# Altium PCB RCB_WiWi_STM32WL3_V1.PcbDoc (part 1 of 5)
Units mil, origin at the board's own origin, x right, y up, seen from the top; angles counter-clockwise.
Board outline 1250.1 x 2647.64 mil, 10 copper layers (L01-TOP, L02-GND, L03-SIG, L04-GND, L05-PWR, L06-PWR, L07-GND, L08-SIG, L09-GND, L10-BOT), stack 62.1 mil thick; 342 components, 203 nets, 969 pads, 708 vias.
Unrouted connection lines stored in the file: 108.
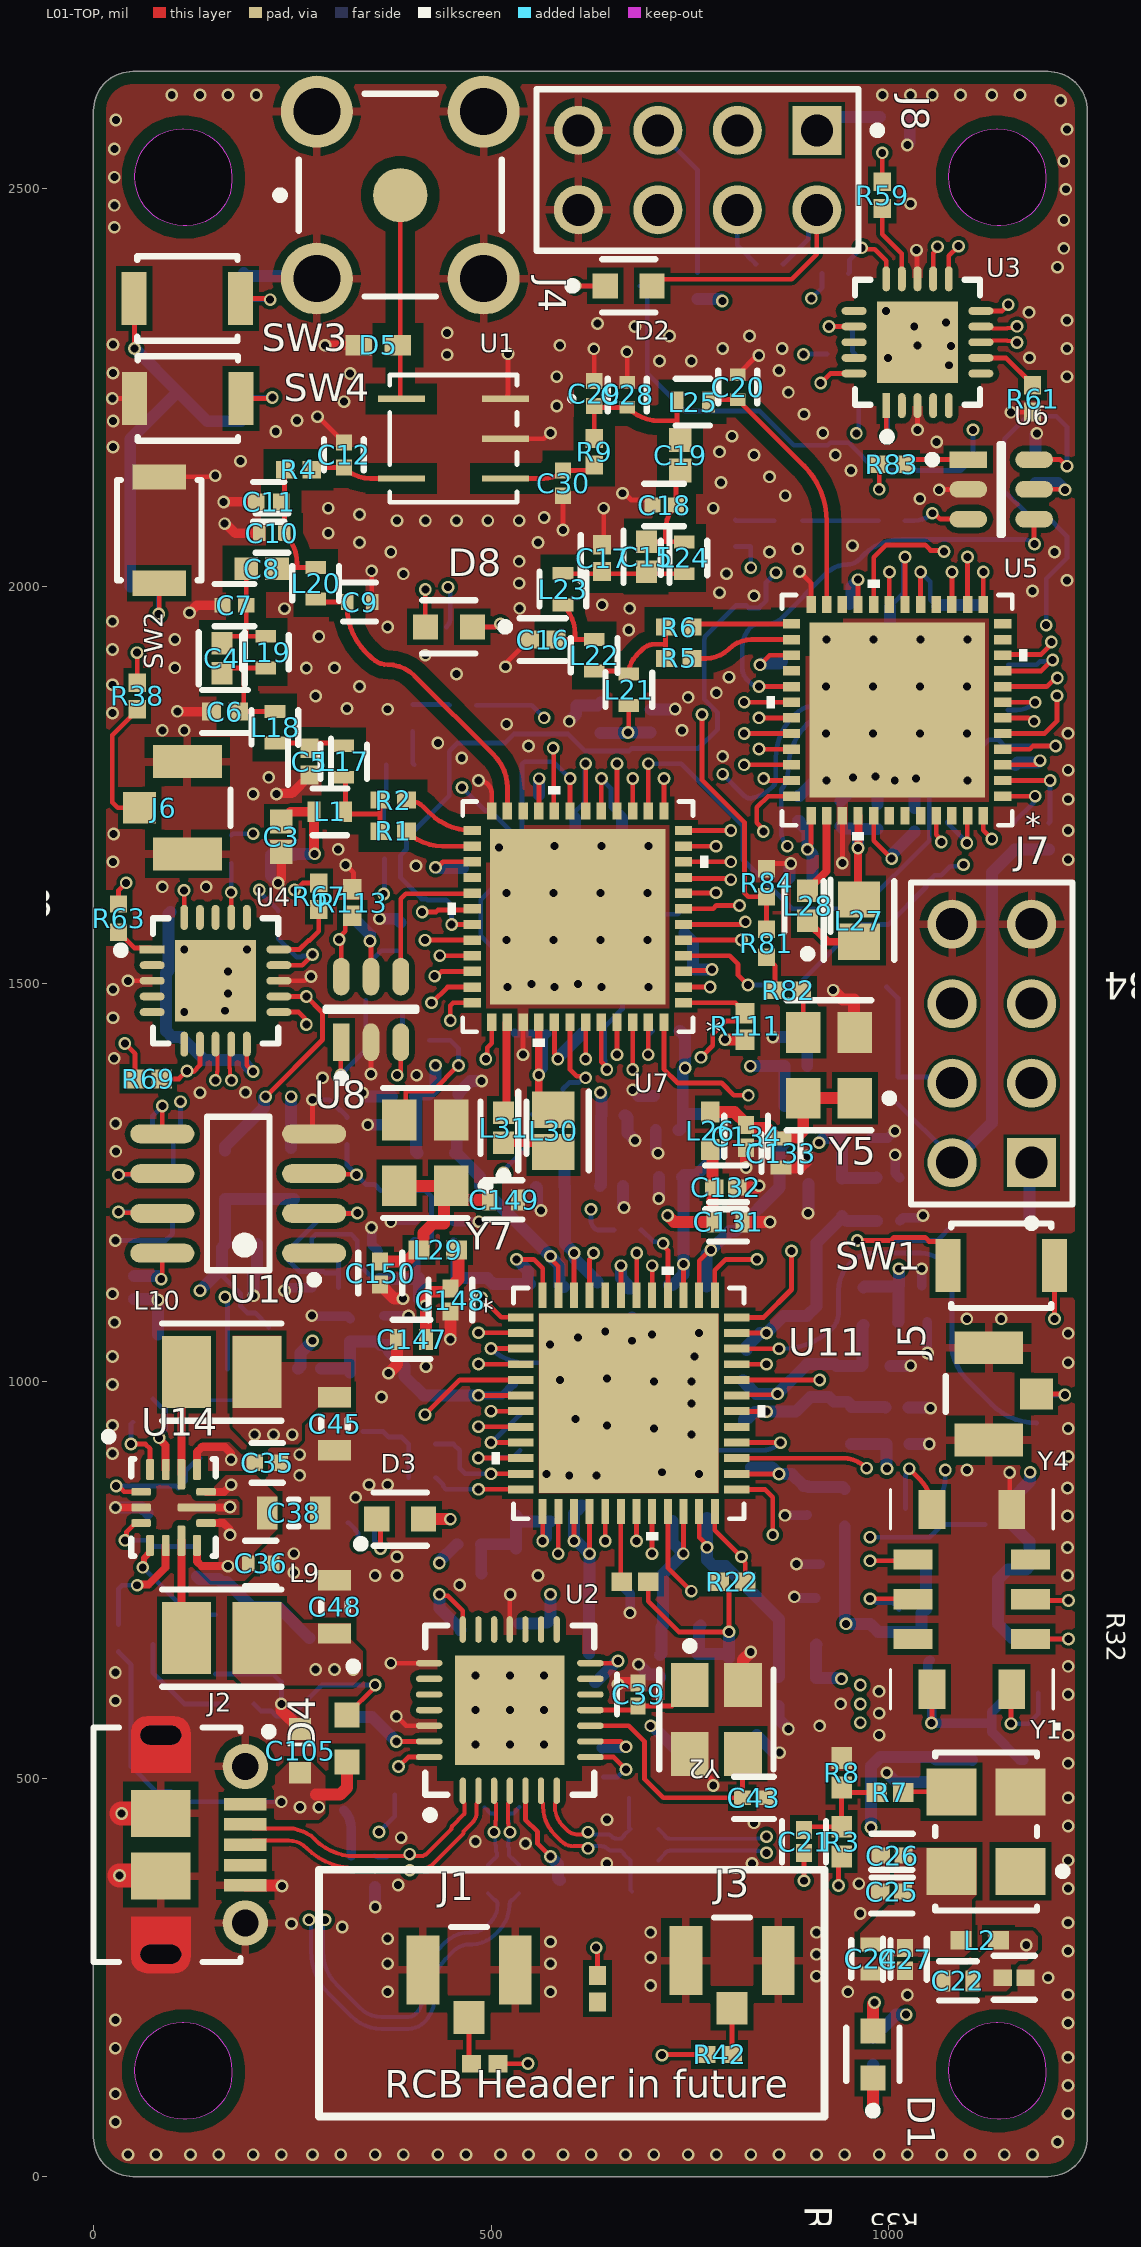
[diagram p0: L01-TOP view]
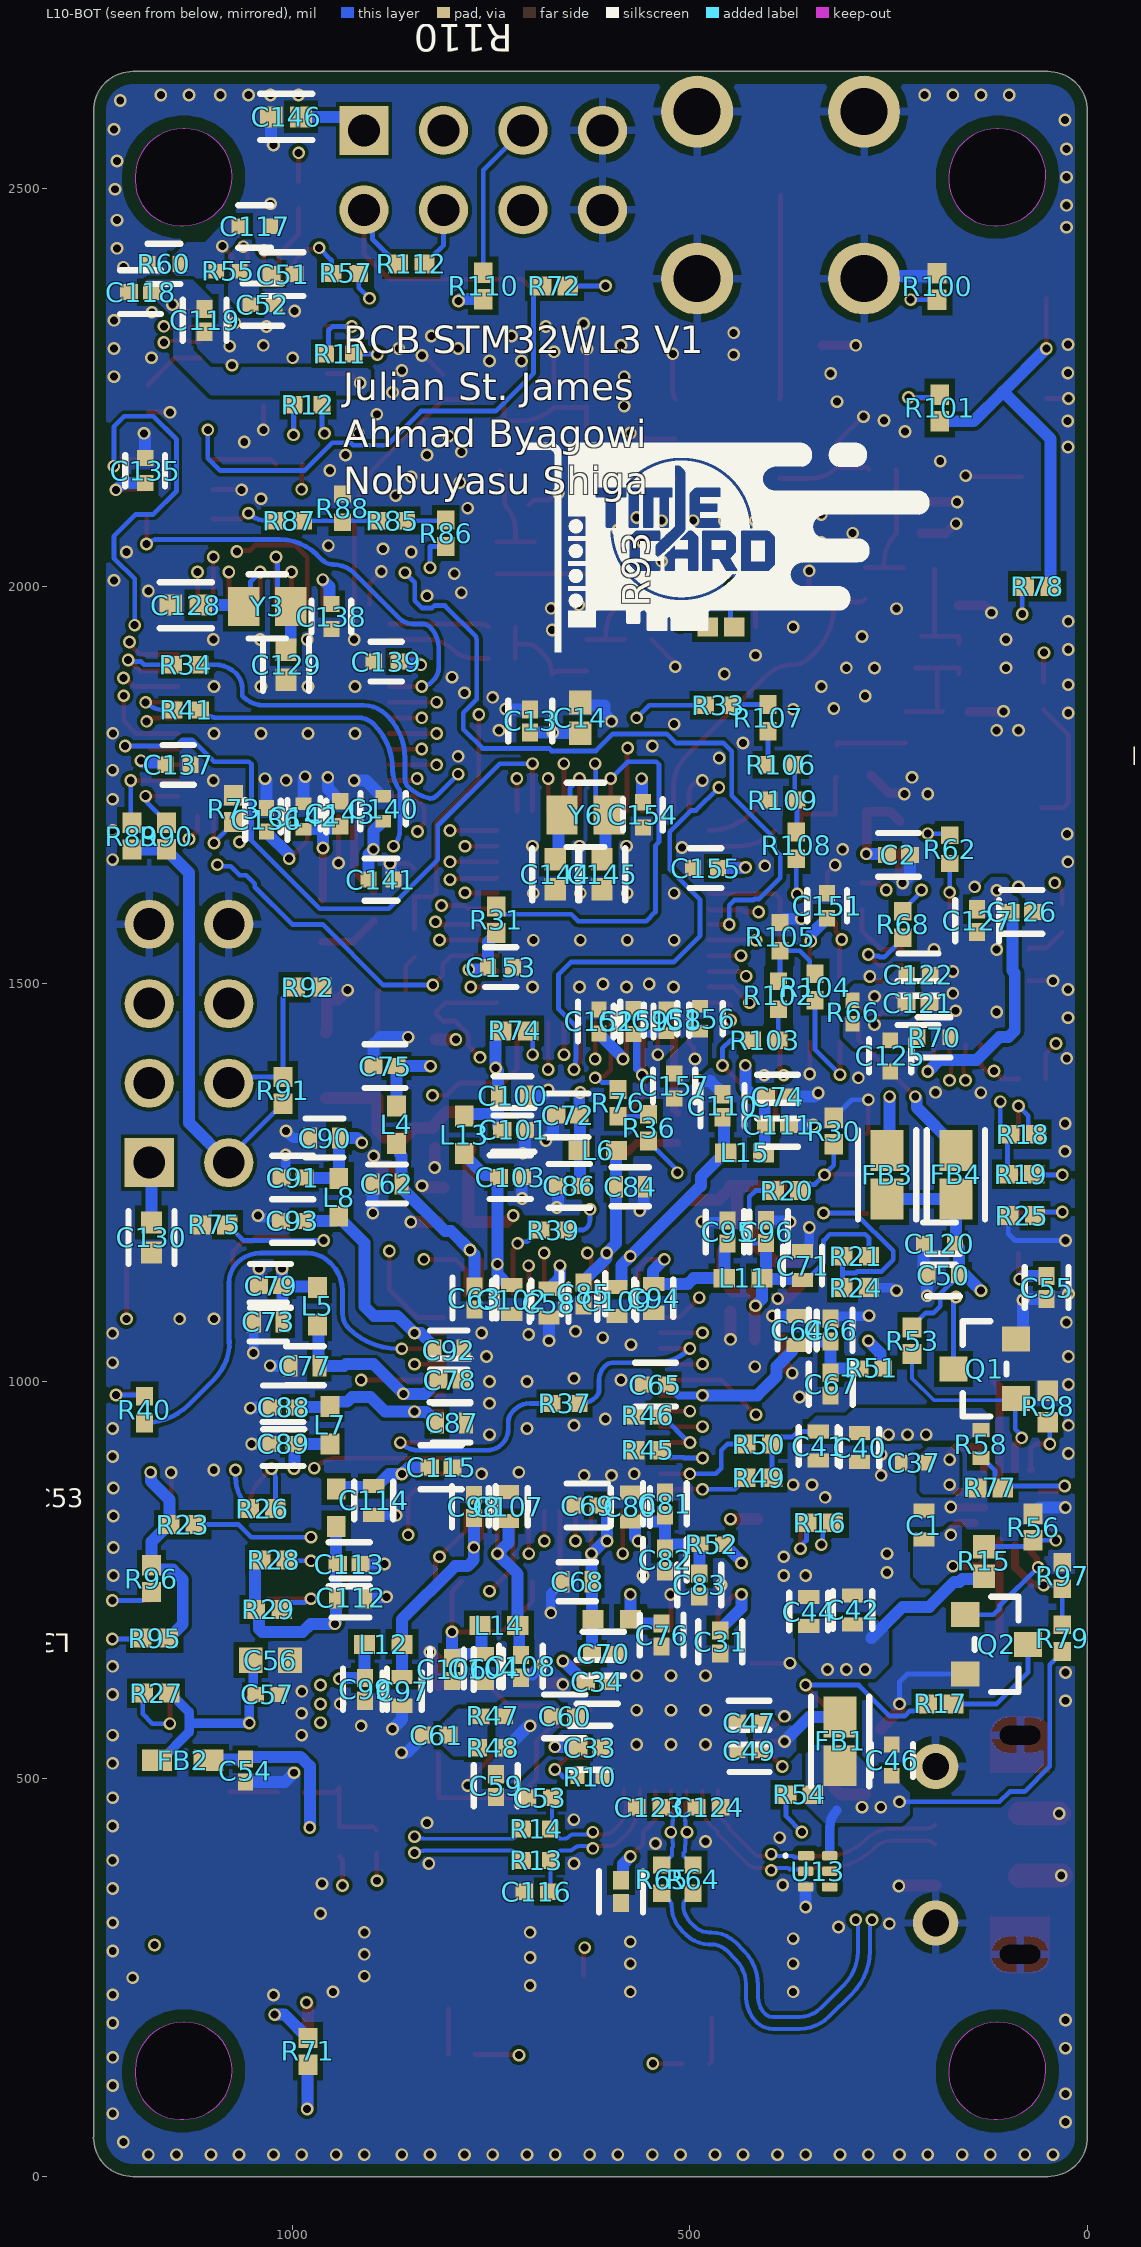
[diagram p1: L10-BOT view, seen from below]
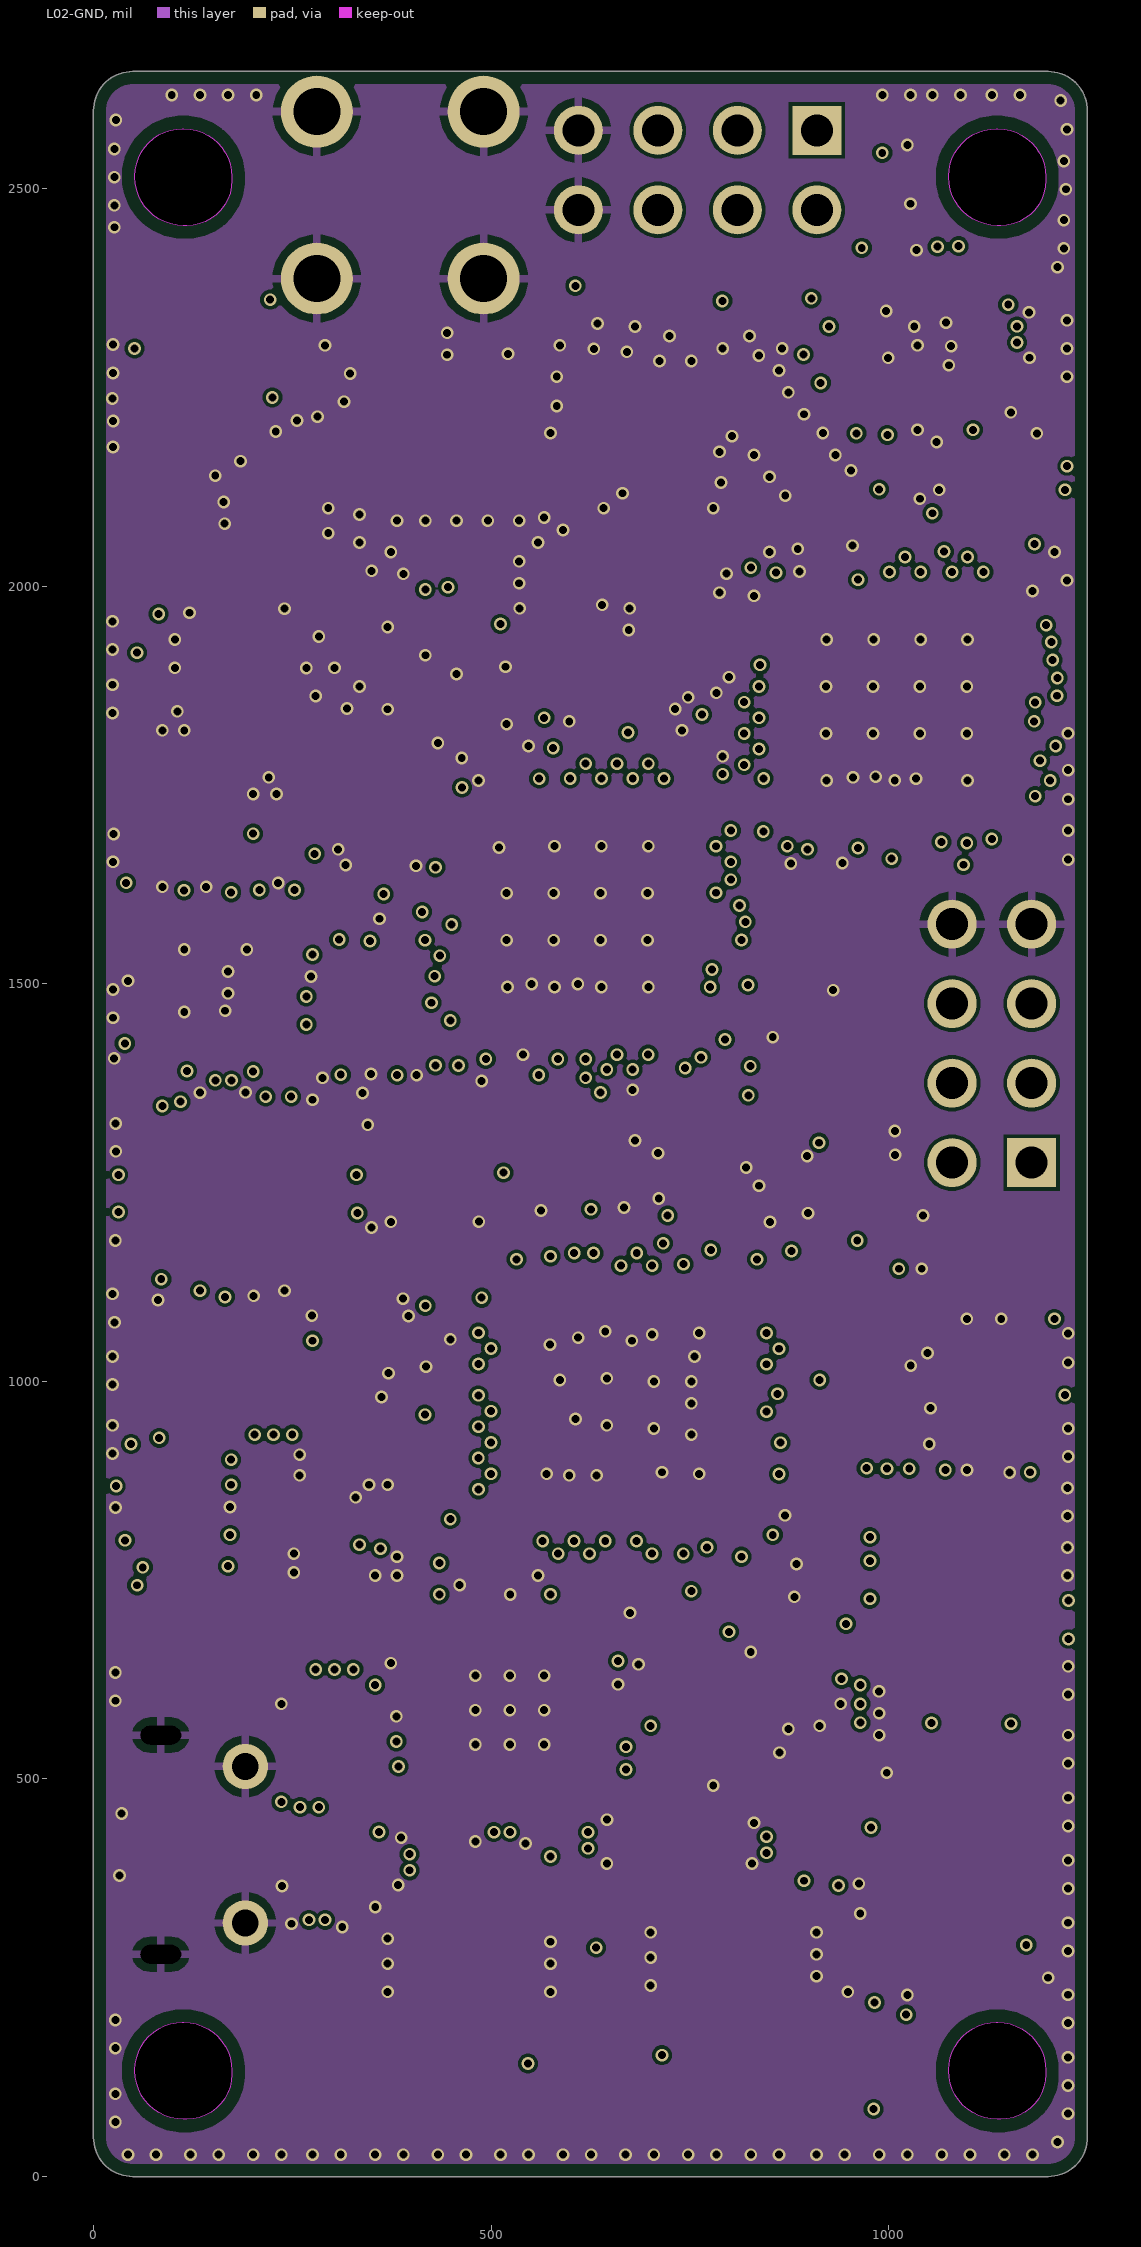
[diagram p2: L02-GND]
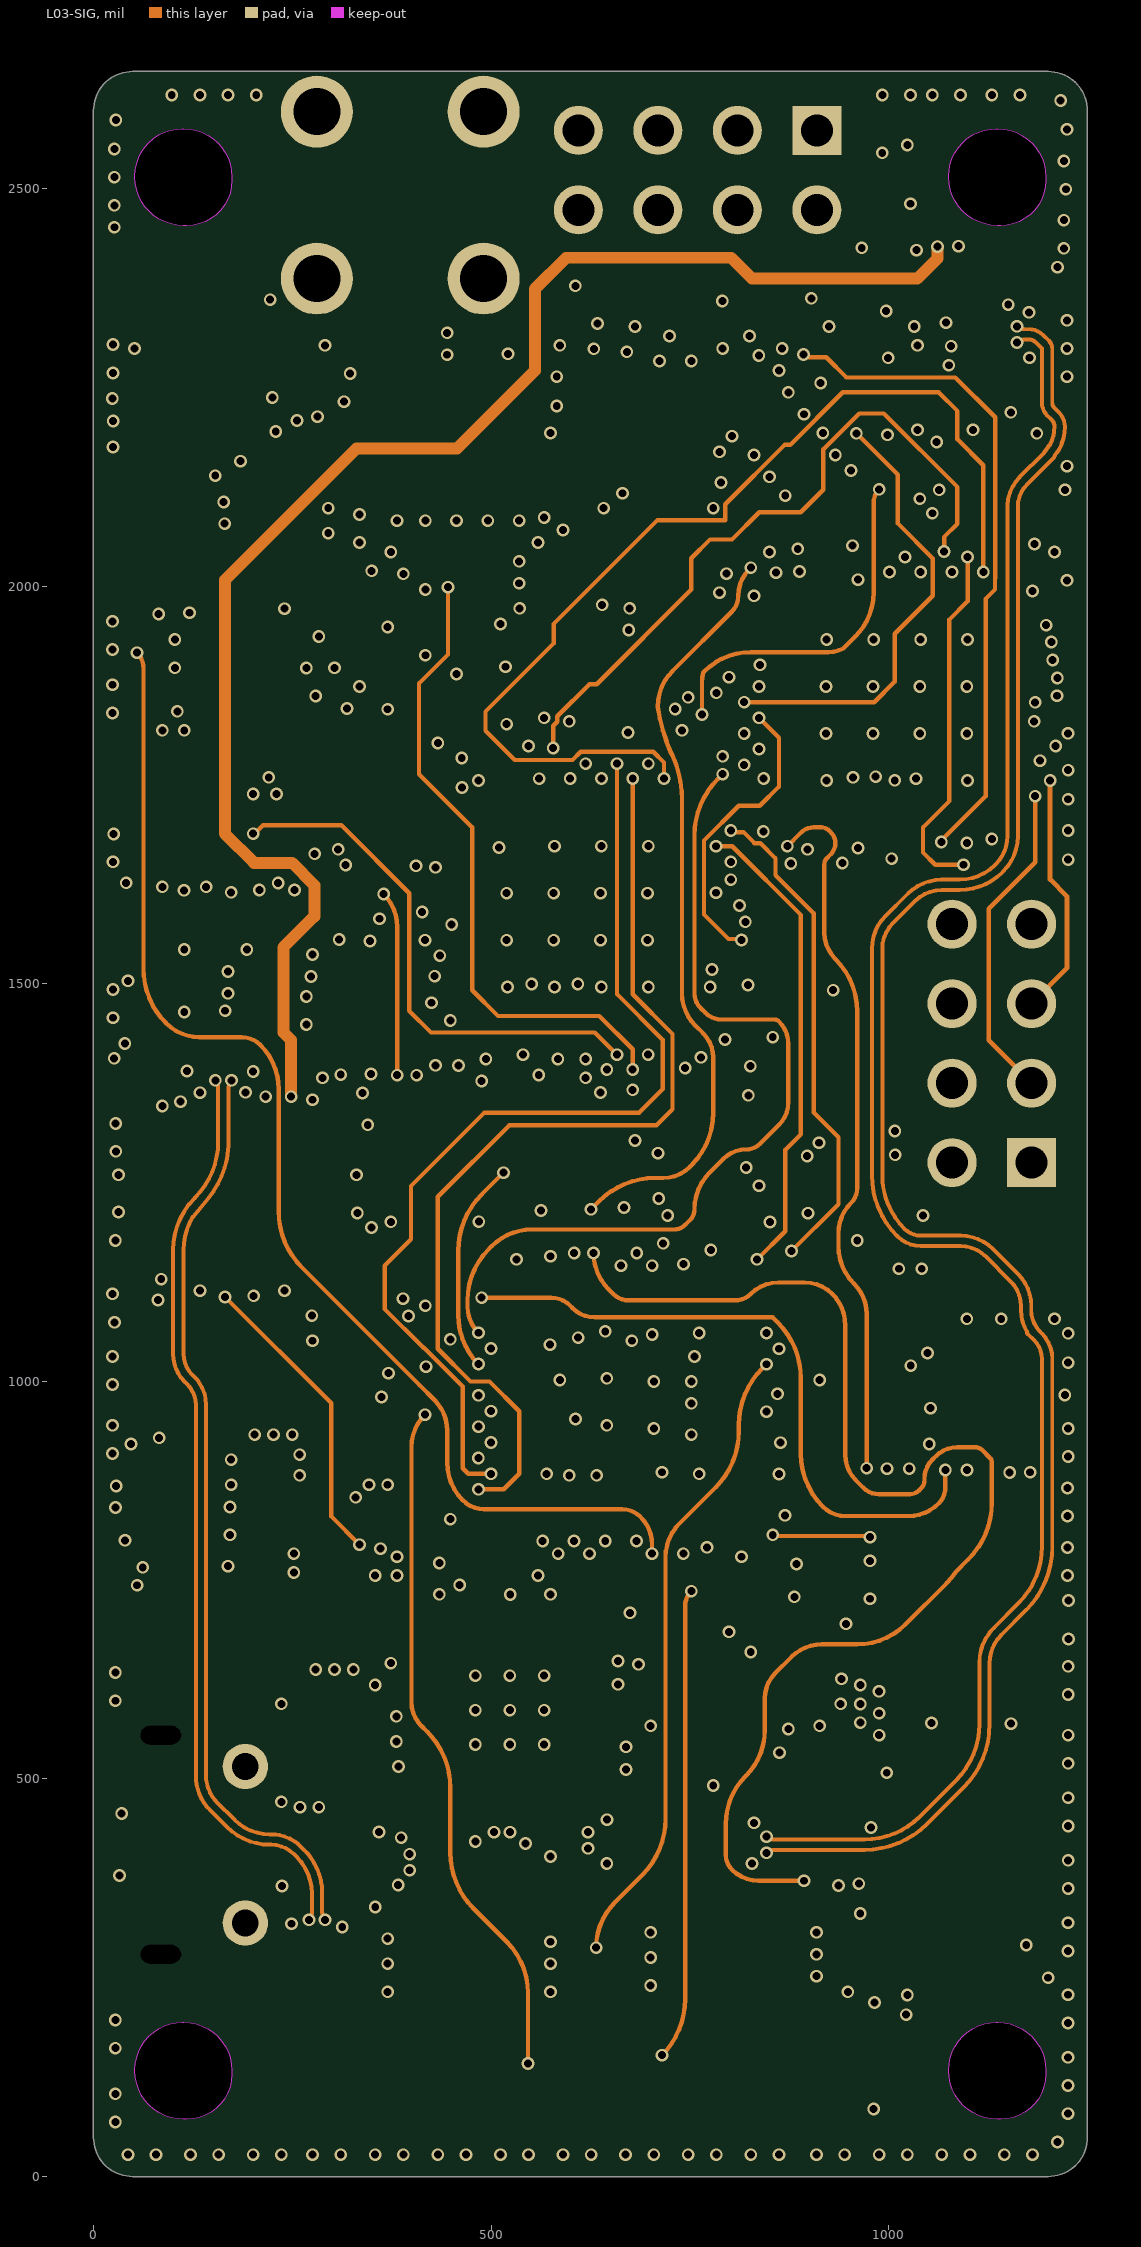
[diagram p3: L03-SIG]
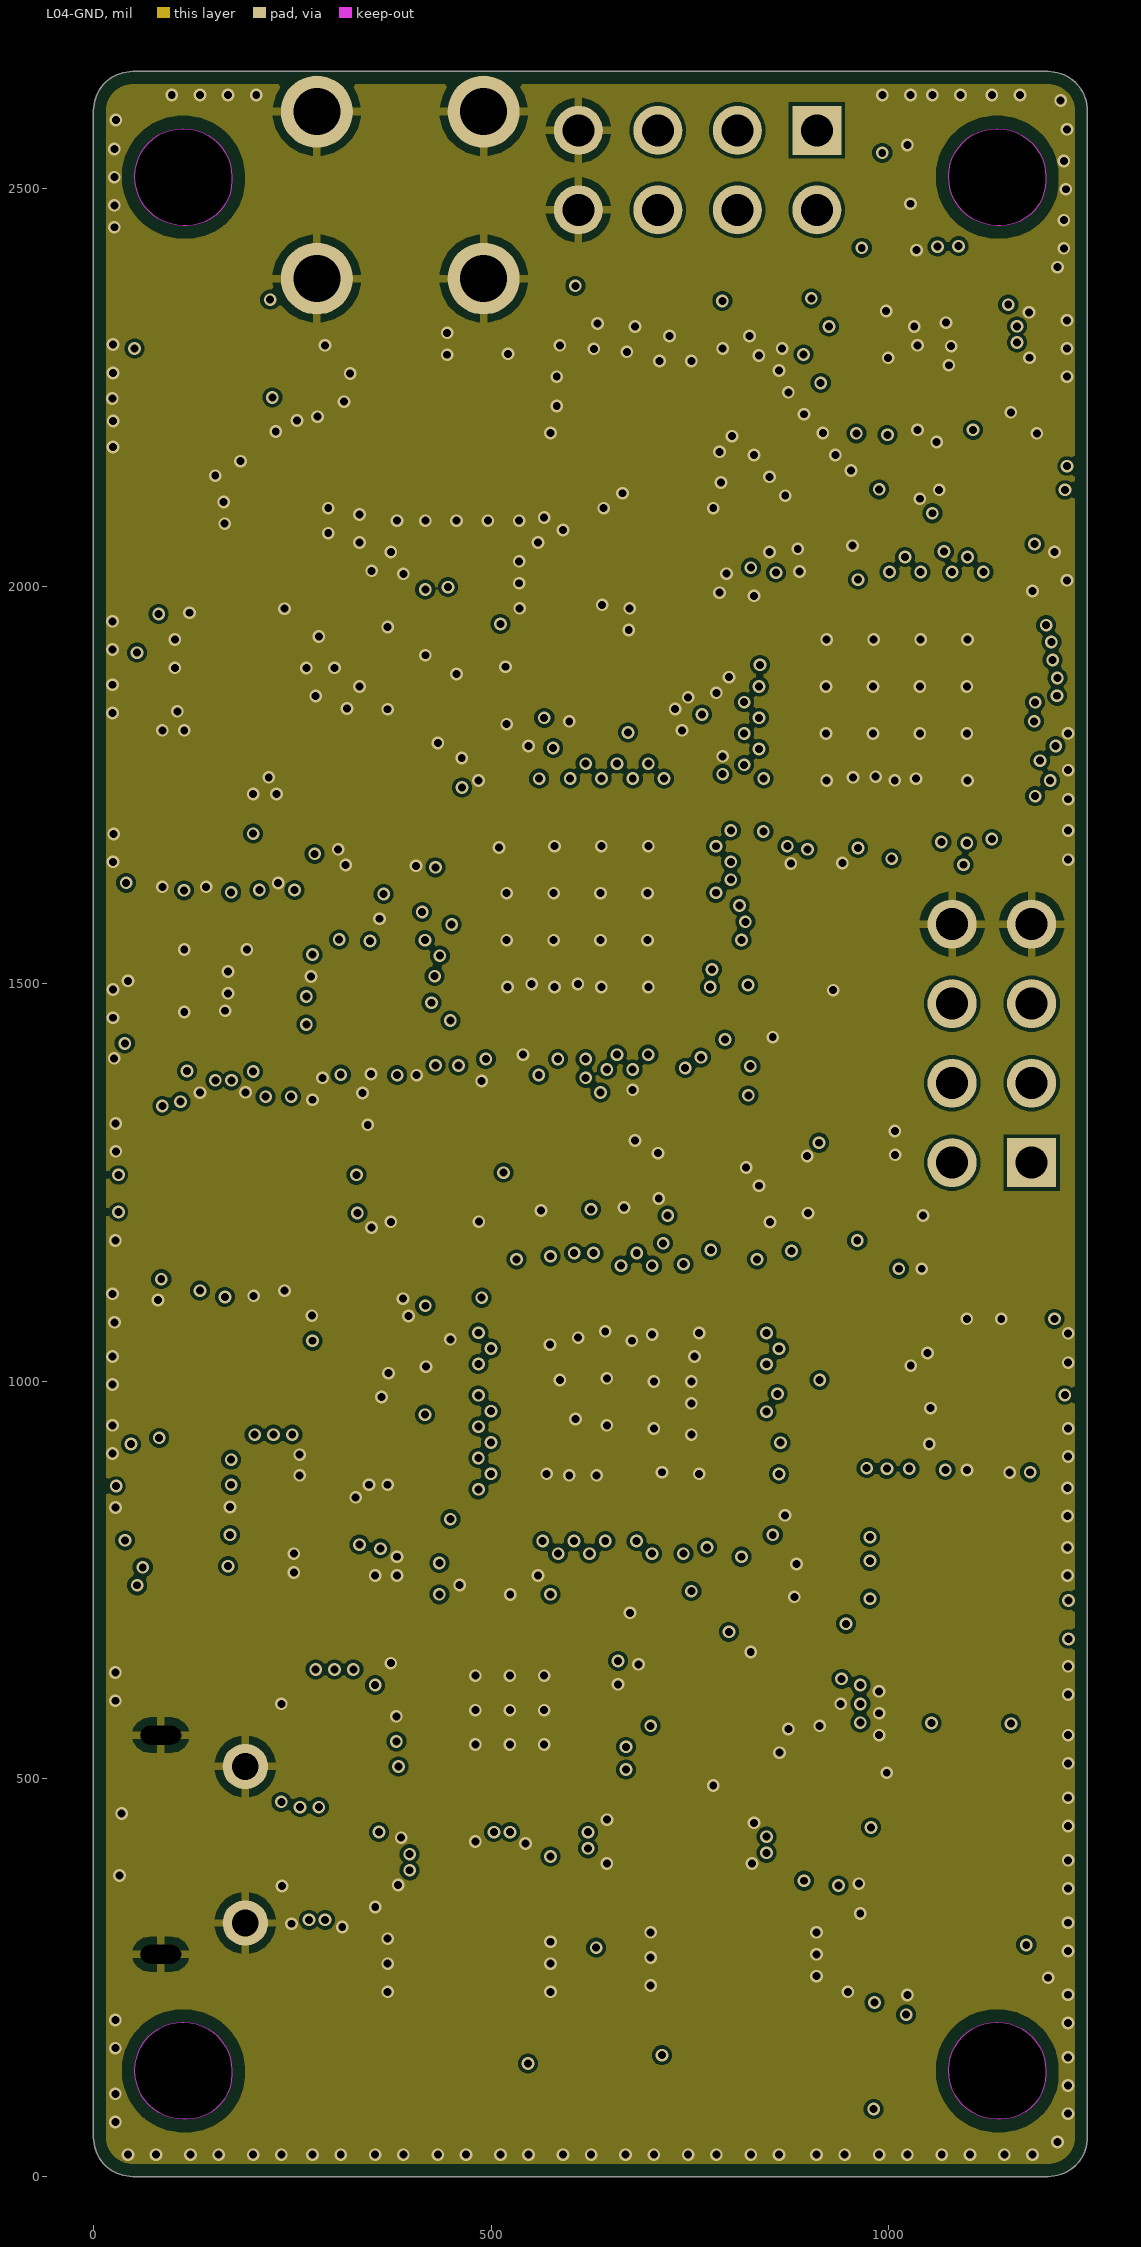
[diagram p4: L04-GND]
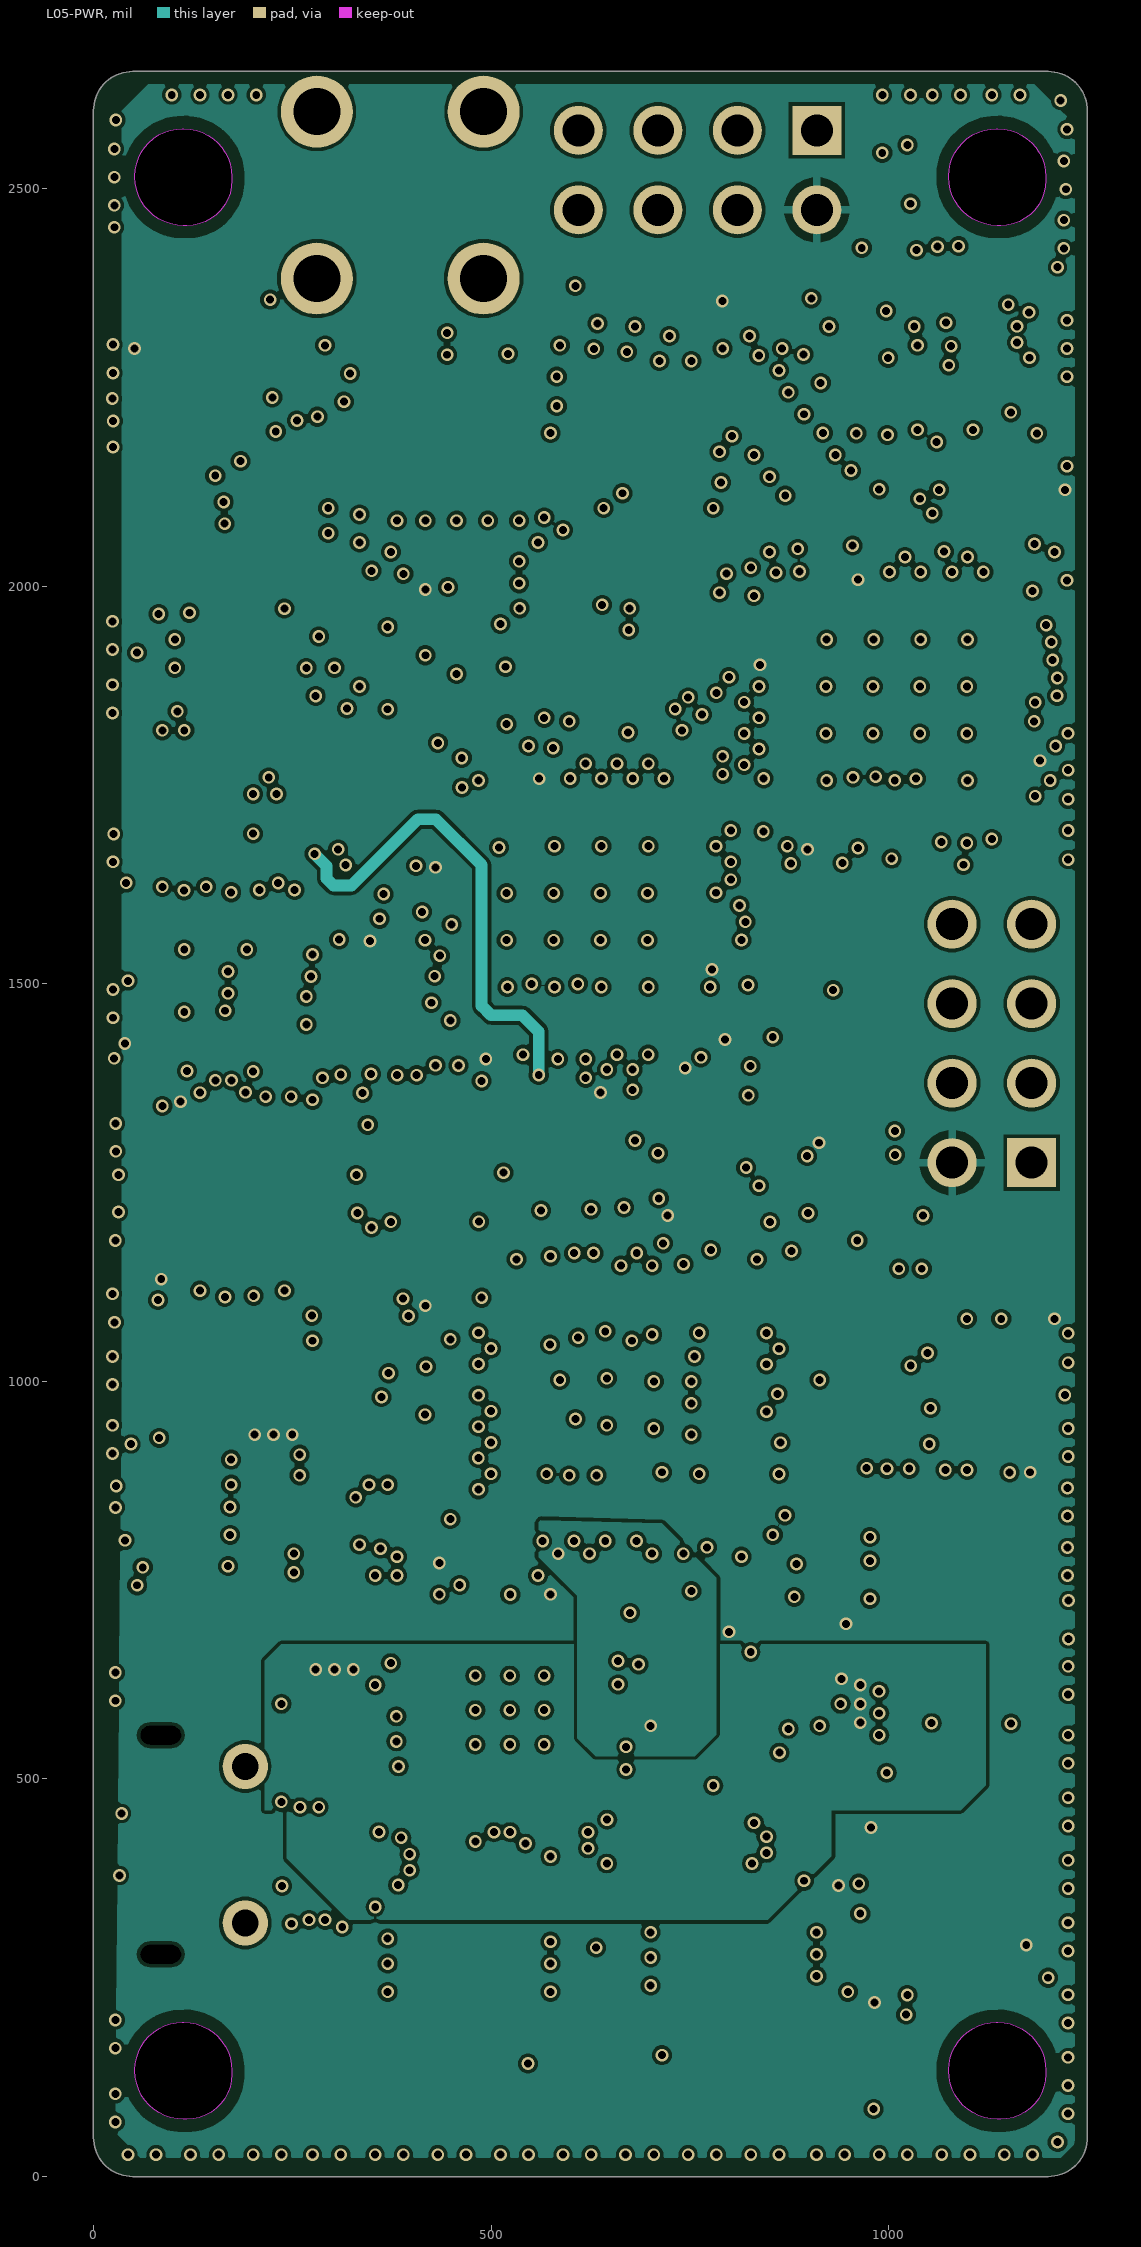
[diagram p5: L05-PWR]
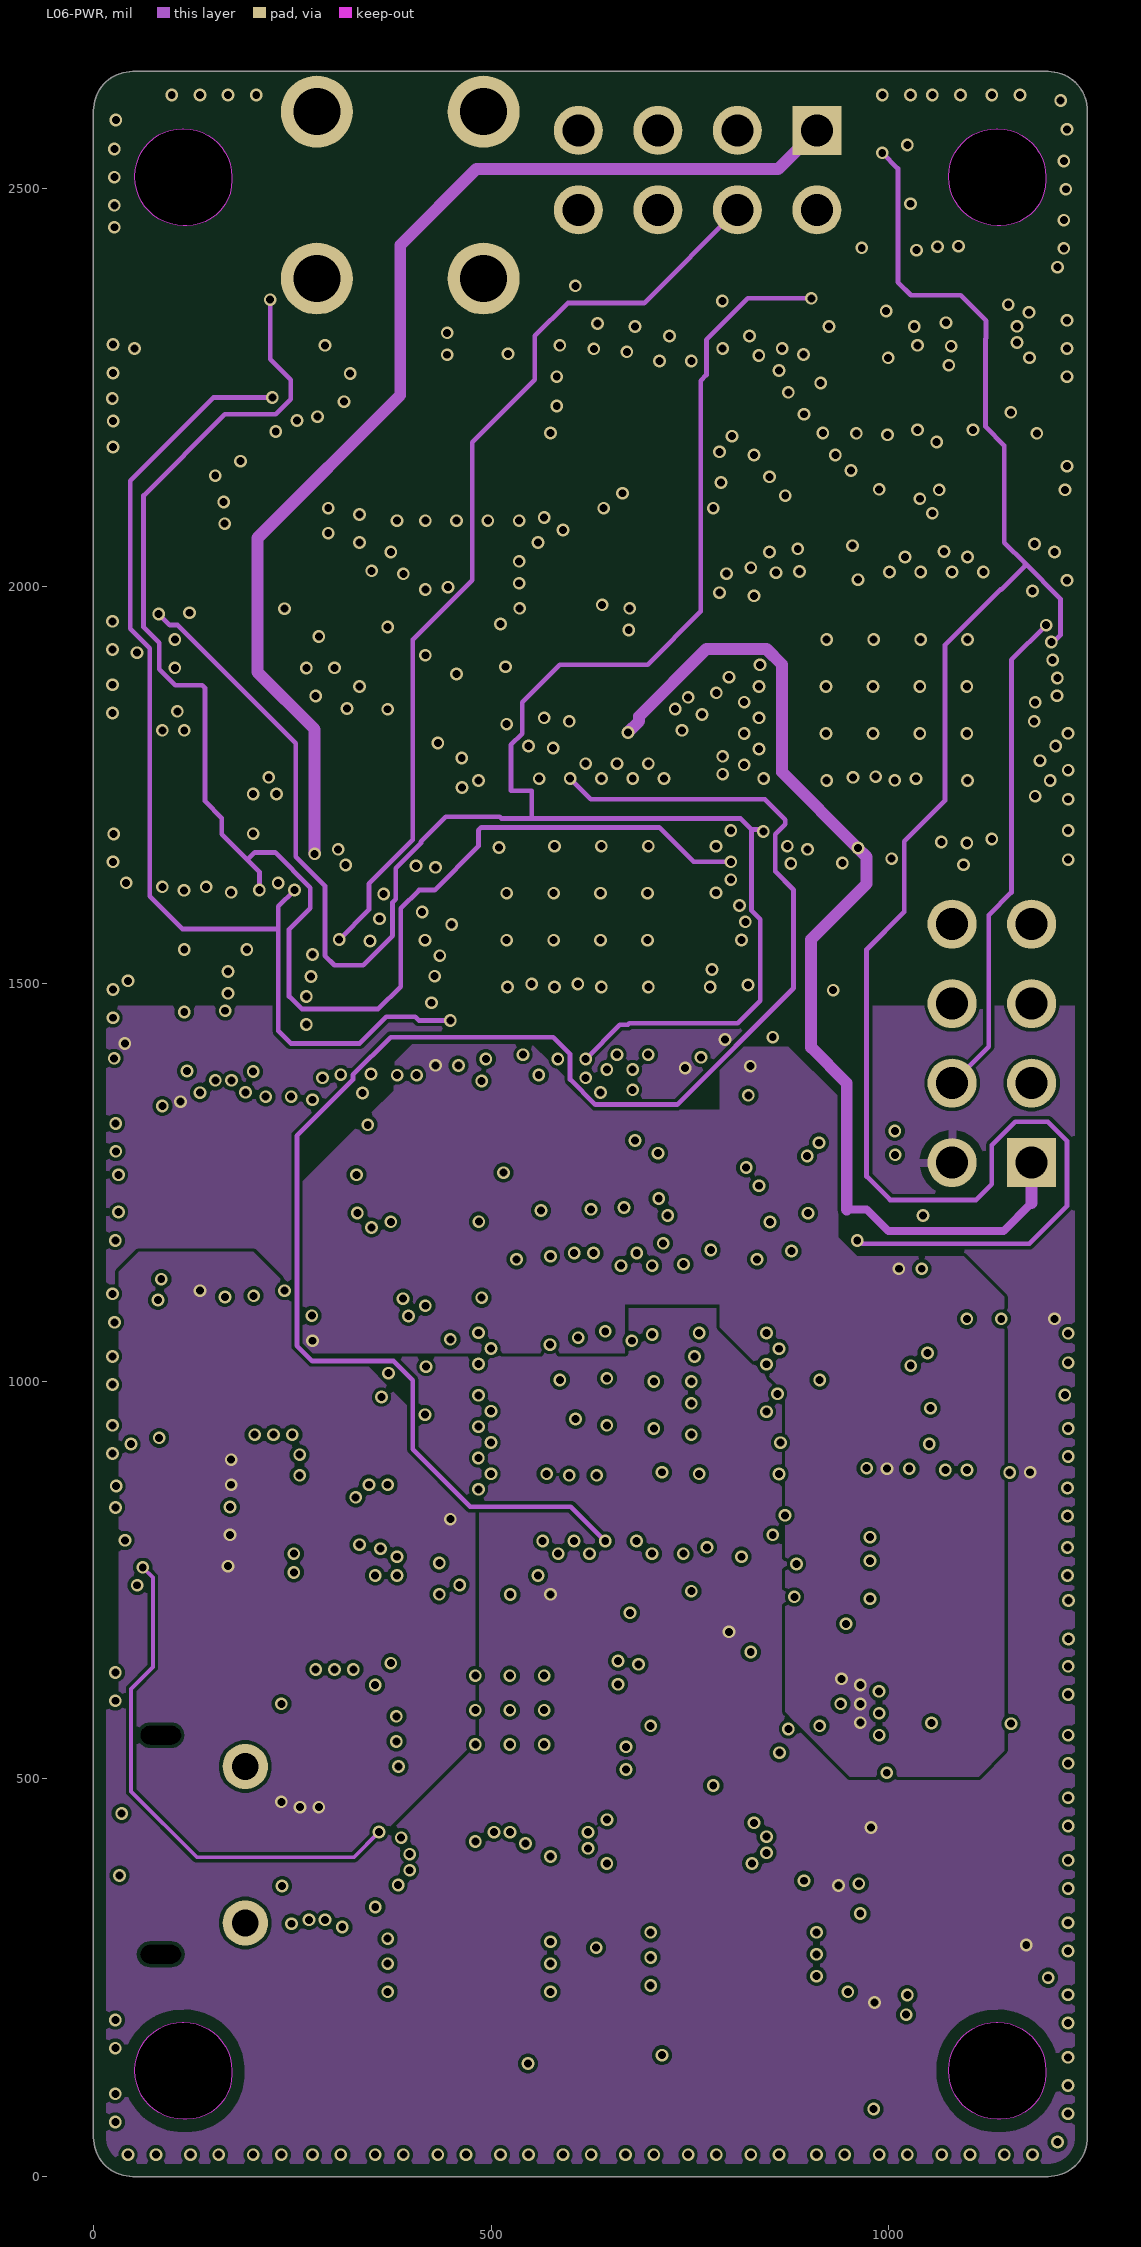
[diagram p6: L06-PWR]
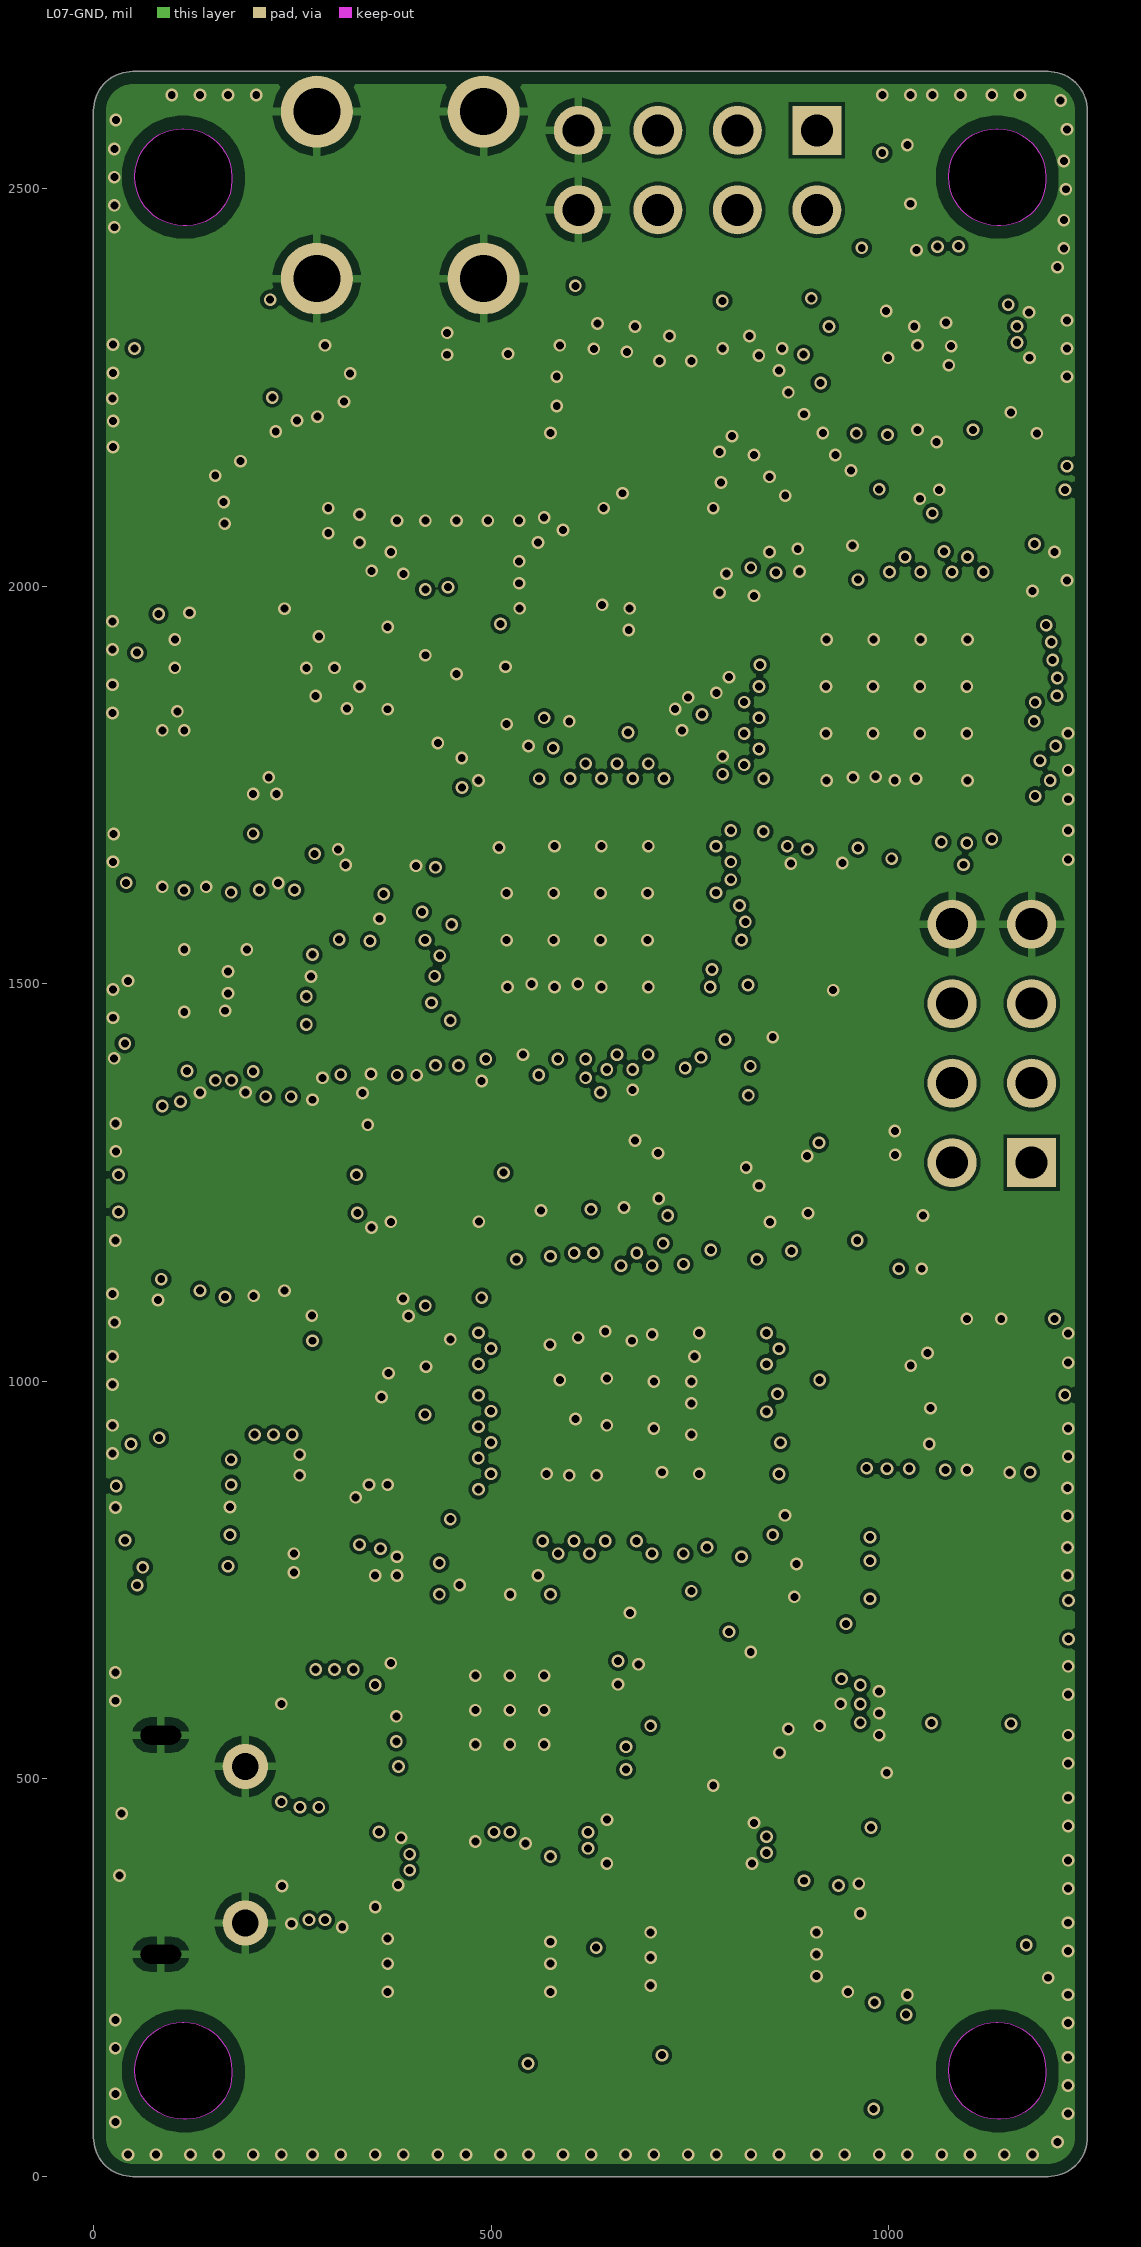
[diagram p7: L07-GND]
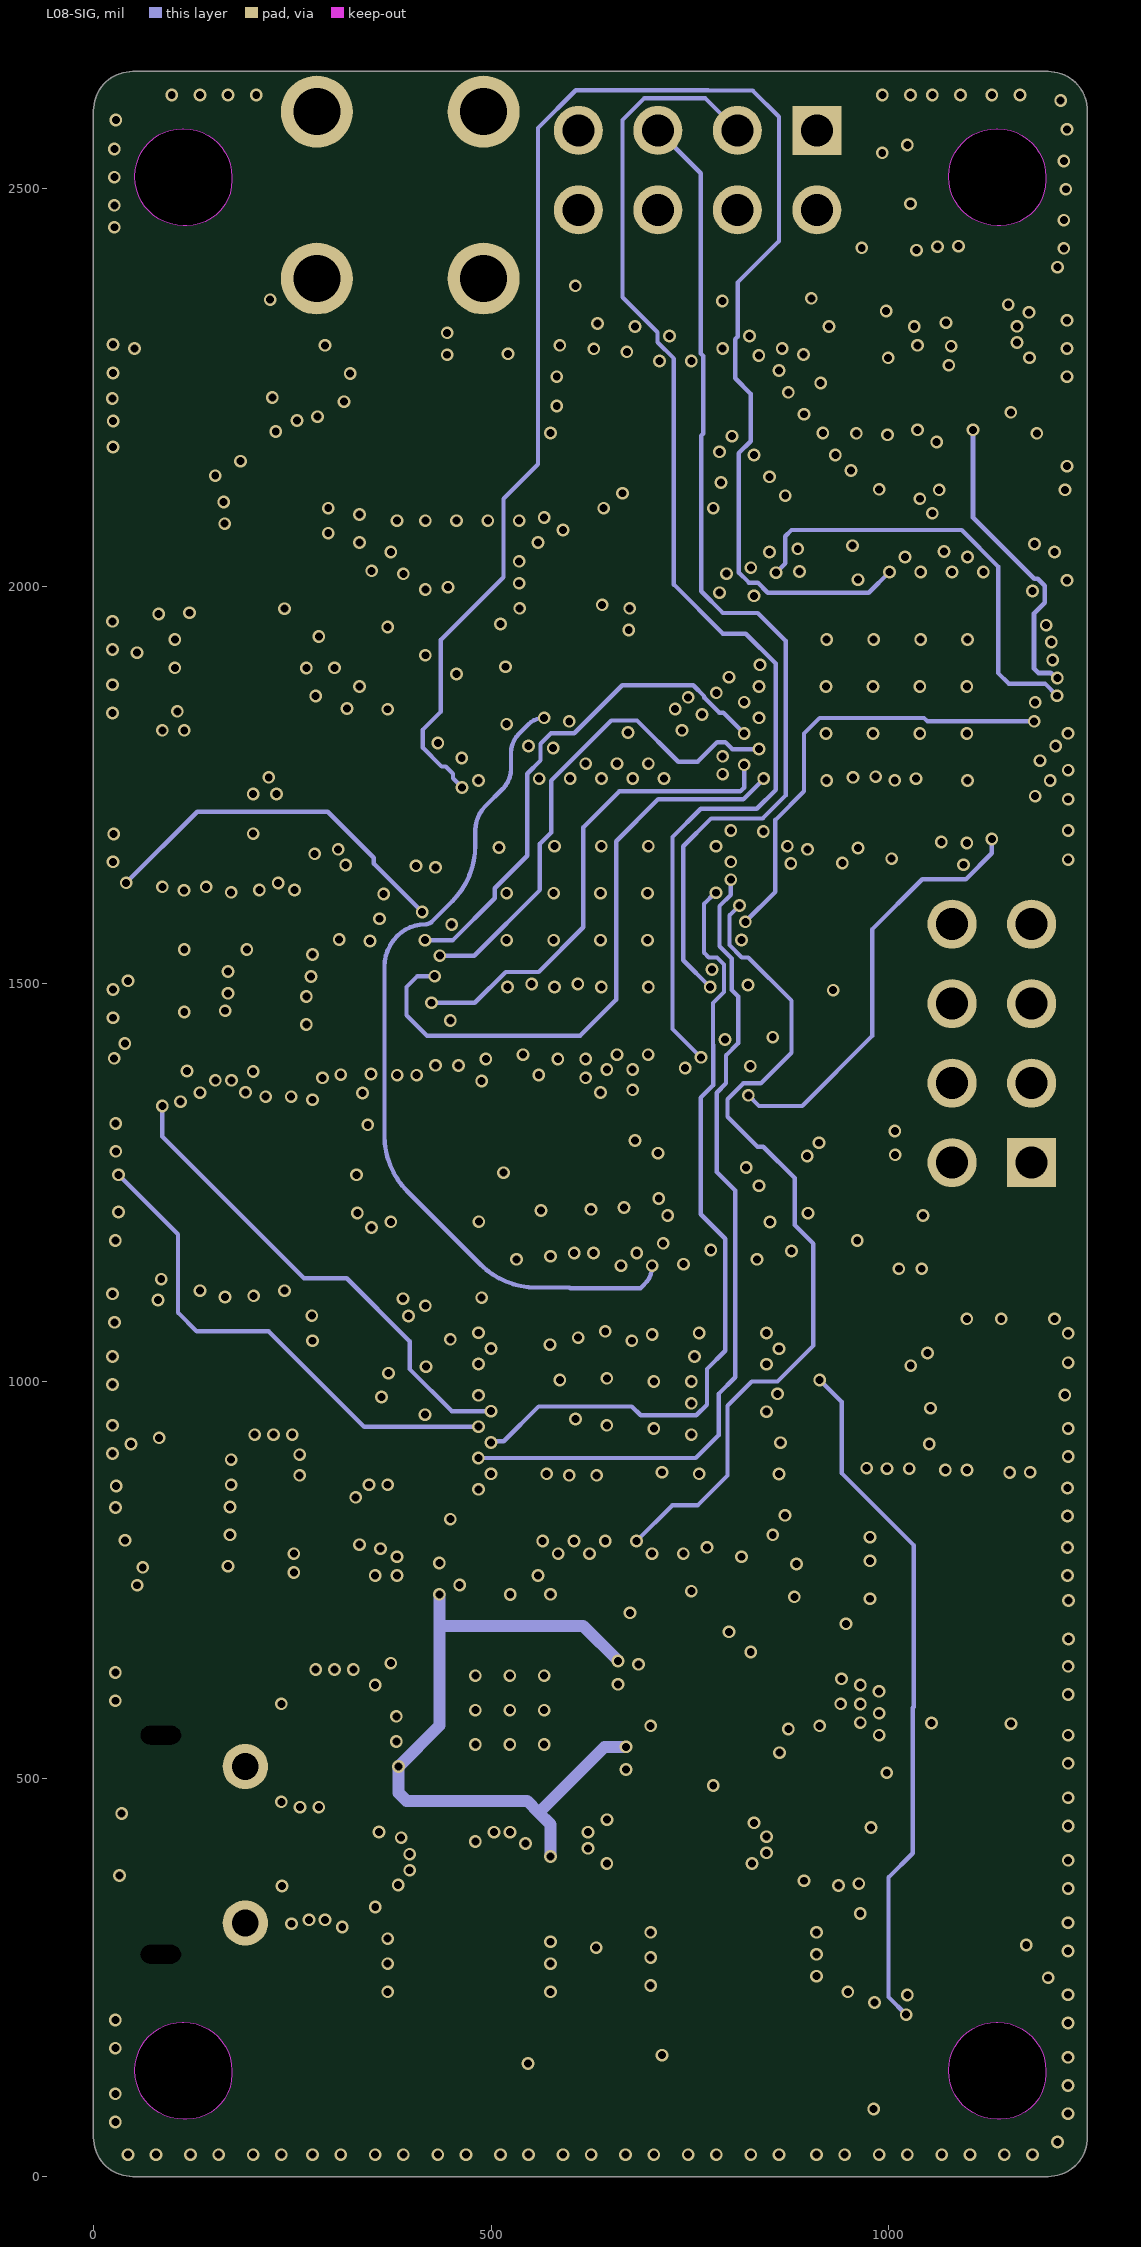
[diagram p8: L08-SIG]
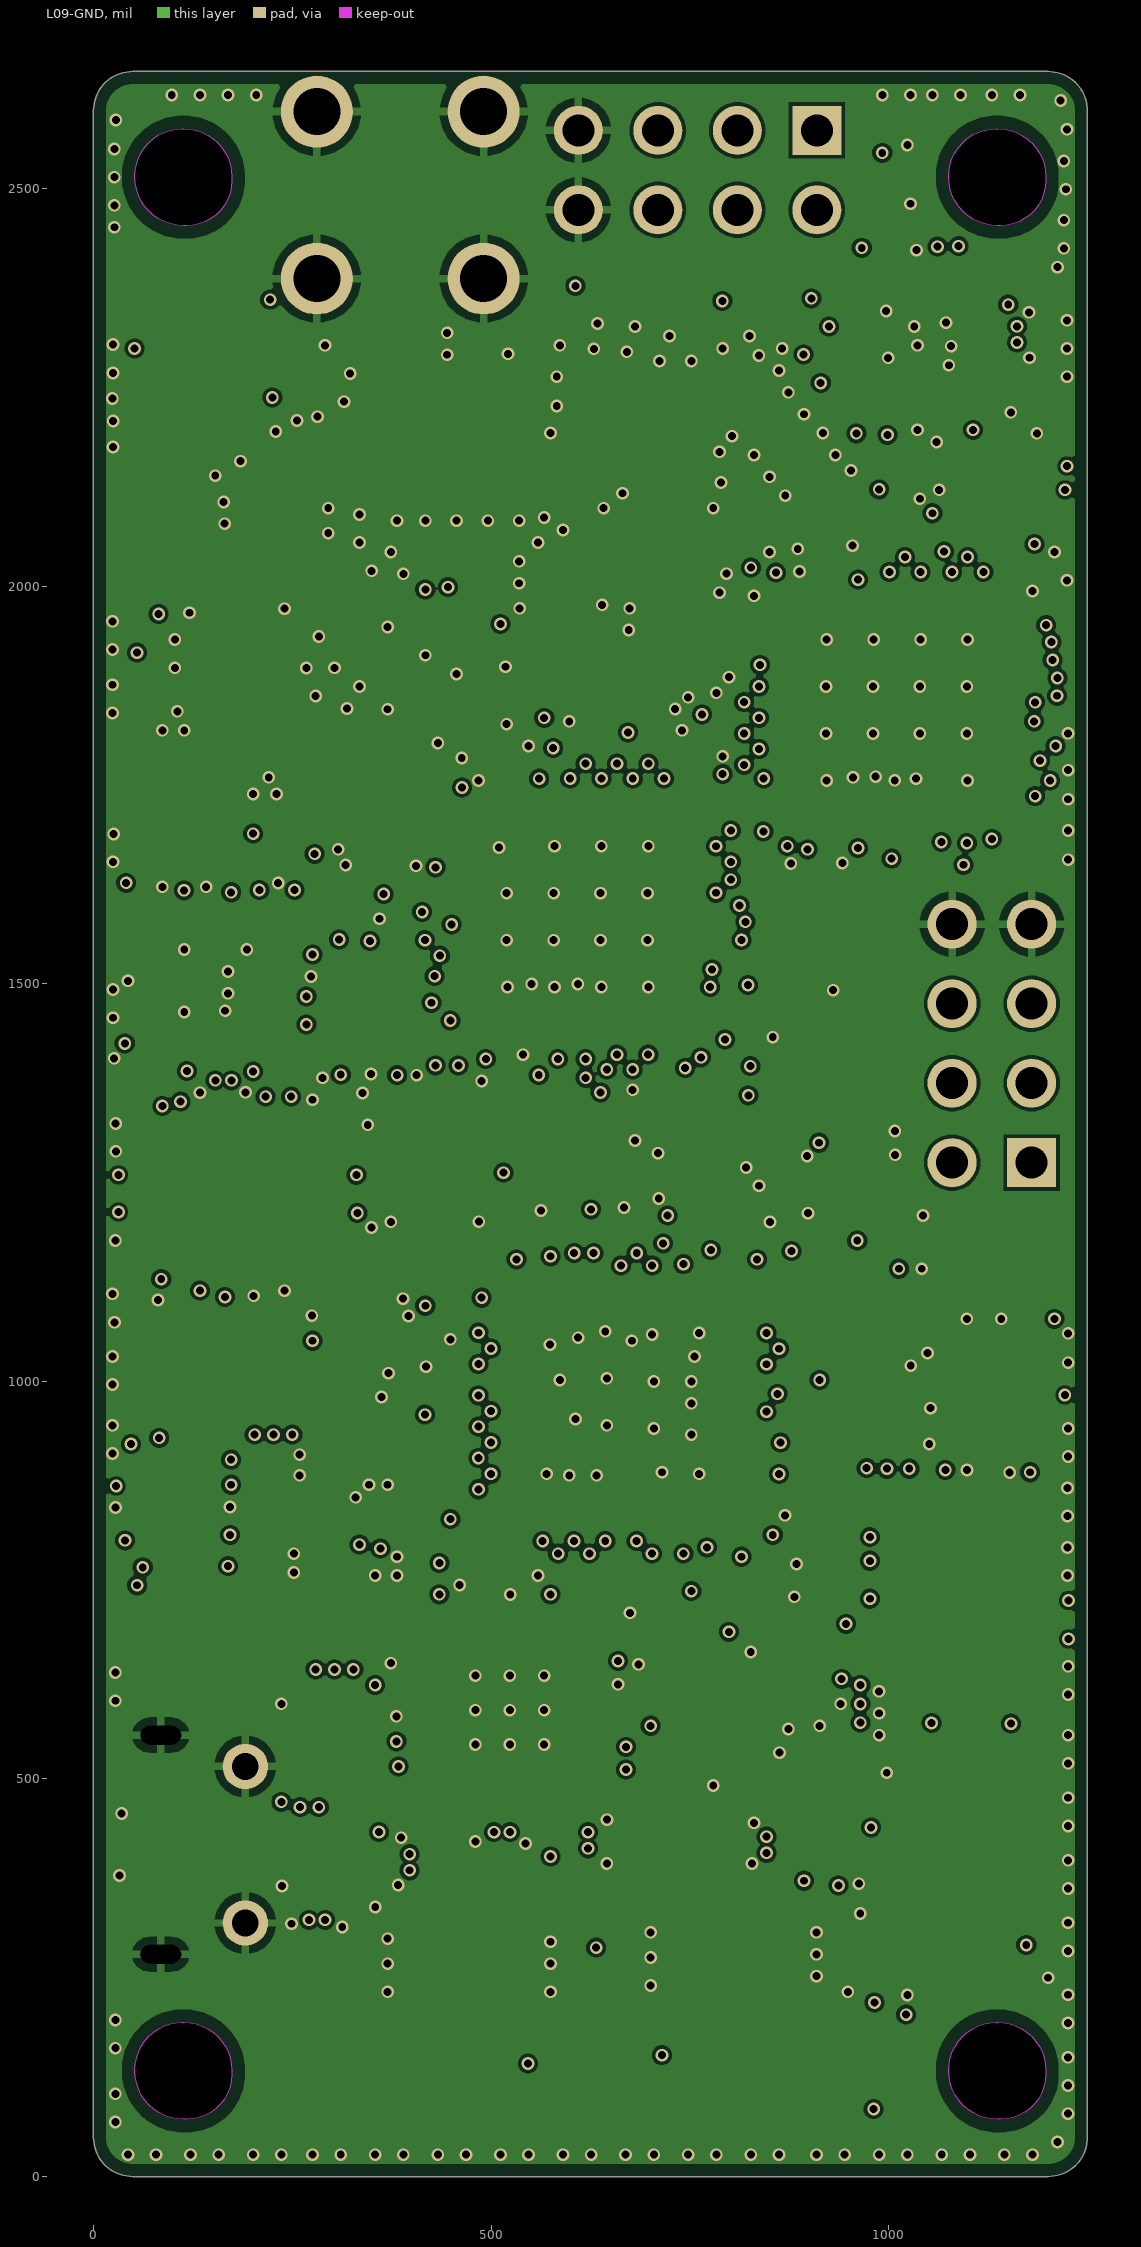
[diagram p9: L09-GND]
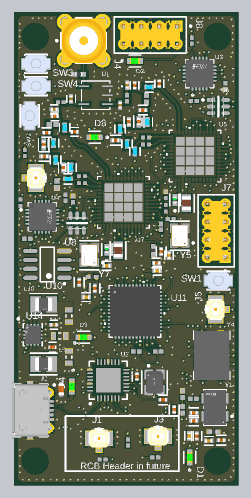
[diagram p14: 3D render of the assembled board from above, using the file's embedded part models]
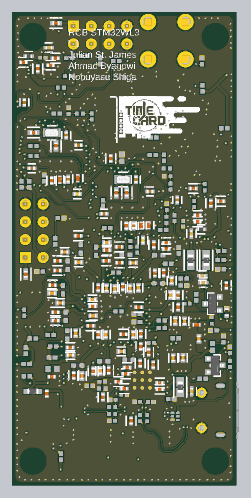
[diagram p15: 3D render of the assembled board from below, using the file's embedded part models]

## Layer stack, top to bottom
L01-TOP: signal copper 1.8
Dielectric 1: prepreg 3.9, 2116, Dk 4.29
L02-GND: signal copper 0.6
Dielectric 4: core 6, PP-006, Dk 4.29
L03-SIG: signal copper 0.6
Dielectric 6: prepreg 7.3, PP-006, Dk 4.29
L04-GND: signal copper 0.6
Dielectric 8: core 6, PP-006, Dk 4.29
L05-PWR: signal copper 0.6
Dielectric 5: prepreg 7.3, PP-006, Dk 4.29
L06-PWR: signal copper 0.6
Dielectric 9: core 6, PP-006, Dk 4.29
L07-GND: signal copper 0.6
Dielectric 7: prepreg 7.3, PP-006, Dk 4.29
L08-SIG: signal copper 0.6
Dielectric 2: core 6, PP-006, Dk 4.29
L09-GND: signal copper 0.6
Dielectric 3: prepreg 3.9, 2116, Dk 4.29
L10-BOT: signal copper 1.8

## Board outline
49.31,0 cw(c49.31,49.31) 0,49.31 0,2598.33 cw(c49.31,2598.33) 49.31,2647.64 1200.79,2647.64 1200.69,2647.64 cw(c1200.69,2598.33) 1250,2598.33 1250,49.31 1250.1,49.31 cw(c1200.79,49.31) 1200.79,0
cut-out: 1137.37,193.9 cw(c1137.37,133.57) 1197.69,133.57 1197.69,128.69 cw(c1140.85,128.69) 1140.85,71.85 1136.75,71.85 cw(c1136.75,132.81) 1075.79,132.81 1075.79,134.11 cw(c1135.57,134.11) 1135.57,193.89
cut-out: 113.75,2575.79 cw(c113.75,2515.46) 174.07,2515.46 174.07,2510.58 cw(c117.23,2510.58) 117.23,2453.74 113.13,2453.74 cw(c113.13,2514.7) 52.17,2514.7 52.17,2516 cw(c111.95,2516) 111.95,2575.78
cut-out: 1137.37,2575.79 cw(c1137.37,2515.46) 1197.69,2515.46 1197.69,2510.58 cw(c1140.85,2510.58) 1140.85,2453.74 1136.75,2453.74 cw(c1136.75,2514.7) 1075.79,2514.7 1075.79,2516 cw(c1135.57,2516) 1135.57,2575.78
cut-out: 113.75,193.9 cw(c113.75,133.57) 174.07,133.57 174.07,128.69 cw(c117.23,128.69) 117.23,71.85 113.13,71.85 cw(c113.13,132.81) 52.17,132.81 52.17,134.11 cw(c111.95,134.11) 111.95,193.89

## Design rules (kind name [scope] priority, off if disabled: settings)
AcuteAngle [All] p1: minimum=6.00000000000000E+0001 checktracksonly=FALSE
BoardOutlineClearance [All] p1: gap=15.75 ignorepadtopadclearanceinfootprint=FALSE
Clearance Clearance_RF [InNetClass('RF')] p1: gap=15 ignorepadtopadclearanceinfootprint=FALSE except(4.3: SMDPad-SMDPad SMDPad-THPad SMDPad-Via SMDPad-Text SMDPad-Hole THPad-THPad THPad-Via THPad-Text THPad-Hole Via-Via Via-Fill Via-Poly Via-Region Via-Text Via-Hole Text-Text Text-Hole)
Clearance [All] p2: gap=4.3 ignorepadtopadclearanceinfootprint=FALSE except(7: SMDPad-Fill SMDPad-Poly SMDPad-Region)
ComponentClearance [All] p1: gap=15.75 collisioncheckmode=3 verticalgap=19.68 showdistances=FALSE
DiffPairsRouting 100_Ohm_Default [InDifferentialPairClass('All Differential Pairs')] p1: maxlimit=10 minlimit=4.43 mostfreqgap=6.68 toplayer_mingap=10 toplayer_prefgap=10 toplayer_minwidth=5 toplayer_maxwidth=5 toplayer_prefwidth=5 midlayer3_mingap=8 midlayer3_maxgap=8 midlayer3_prefgap=8 midlayer3_minwidth=5 midlayer3_maxwidth=5 midlayer3_prefwidth=5 midlayer4_mingap=8 midlayer4_maxgap=8 midlayer4_prefgap=8 midlayer4_minwidth=5 midlayer4_maxwidth=5 midlayer4_prefwidth=5 bottomlayer_mingap=10 bottomlayer_prefgap=10 bottomlayer_minwidth=5 bottomlayer_maxwidth=5 bottomlayer_prefwidth=5 impedanceprofiledriven=TRUE impedanceprofileid={6D9B781E-2234-44CB-9805-C73247B854E7} impedanceprofilevalue=100.000000 maxuncoupledlength=200
HoleSize [All] p1: absolutevalues=TRUE maxlimit=118.11 minlimit=5.91 maxpercent=80.000 minpercent=20.000
HoleToHoleClearance [All] p1: gap=11.81 allowstackedmicrovias=TRUE
MatchedLengths [InDifferentialPairClass('All Differential Pairs')] p1: tolerance=10 checknetsindiffpair=TRUE checkdiffpairvsdiffpair=FALSE checkxsignals=FALSE checkothers=FALSE
MinimumSolderMaskSliver [All] p1: minsoldermaskwidth=3.94 // 0.076mm for Green Soldermask, 0.1 for other color soldermask
PlaneClearance [All] p1: clearance=10
PolygonConnect TH_PolyConnect [HasFootprint('FP-SMA-J-P-H-ST-MT1-MFG') OR HasFootprint('FP-HTSW-104-07-G-D-MFG') OR HasFootprint('USB-MICRO-B_V') OR HasFootprint('FP-U_FL-R-SMT-1_10-MFG')] p1: connectstyle=Relief reliefconductorwidth=10 reliefentries=4 polygonreliefangle="90 Angle" airgapwidth=10
PolygonConnect [All] p2: connectstyle=Direct reliefconductorwidth=20 reliefentries=4 polygonreliefangle="90 Angle" airgapwidth=10
RoutingCorners [All] p1: cornerstyle=45-Degree minsetback=98.43 maxsetback=98.43
RoutingVias [All] p1: holewidth=10 width=16 viastyle="Through Hole" minholewidth=10 minwidth=16 maxholewidth=11.81 maxwidth=23.62
SilkToSilkClearance [All] p1: silktosilkclearance=3.94
SilkToSolderMaskClearance [IsPad] p1: minsilkscreentomaskgap=5 clearancetoexposedcopper=TRUE
SolderMaskExpansion [All] p1: expansion=1.97 istentingtop=FALSE
SupplyNets "Schematic Supply Nets_24" [InNet('TX_VFBSD')] p1: voltage=0.000
SupplyNets "Schematic Supply Nets_23" [InNet('RX_VFBSD')] p2: voltage=0.000
SupplyNets "Schematic Supply Nets_22" [InNet('RX_VDD')] p3: voltage=0.000
SupplyNets "Schematic Supply Nets_21" [InNet('TX_VDD')] p4: voltage=0.000
SupplyNets "Schematic Supply Nets_20" [InNet('DPLL_VDD_GPIO')] p5: voltage=0.000
SupplyNets "Schematic Supply Nets_19" [InNet('DPLL_VDDA_FB')] p6: voltage=0.000
SupplyNets "Schematic Supply Nets_18" [InNet('DPLL_VDDO_Q9')] p7: voltage=0.000
SupplyNets "Schematic Supply Nets_17" [InNet('DPLL_VDDA_BG_LC')] p8: voltage=0.000
SupplyNets "Schematic Supply Nets_16" [InNet('DPLL_VDDA_PDCP_XTAL')] p9: voltage=0.000
SupplyNets "Schematic Supply Nets_15" [InNet('P1V8')] p10: voltage=0.000
SupplyNets "Schematic Supply Nets_14" [InNet('DPLL_VDD_DCO_Q11')] p11: voltage=0.000
SupplyNets "Schematic Supply Nets_13" [InNet('P3V3')] p12: voltage=0.000
SupplyNets "Schematic Supply Nets_12" [InNet('GND')] p13: voltage=0.000
SupplyNets "Schematic Supply Nets_11" [InNet('DPLL_VDD_DCO_Q9')] p14: voltage=0.000
SupplyNets "Schematic Supply Nets_10" [InNet('DPLL_VDD_DCO_Q10')] p15: voltage=0.000
SupplyNets "Schematic Supply Nets_9" [InNet('DPLL_VDDO_Q10')] p16: voltage=0.000
SupplyNets "Schematic Supply Nets_8" [InNet('DPLL_VDD_DIG')] p17: voltage=0.000
SupplyNets "Schematic Supply Nets_7" [InNet('VIN')] p18: voltage=0.000
SupplyNets "Schematic Supply Nets_6" [InNet('DPLL_VDD_DCO_Q8')] p19: voltage=0.000
SupplyNets "Schematic Supply Nets_5" [InNet('DPLL_VDDO_Q8')] p20: voltage=0.000
SupplyNets "Schematic Supply Nets_4" [InNet('DPLL_VDD_CLK')] p21: voltage=0.000
SupplyNets "Schematic Supply Nets_3" [InNet('DPLL_VDDO_Q11')] p22: voltage=0.000
SupplyNets "Schematic Supply Nets_2" [InNet('RP_CORE')] p23: voltage=0.000
SupplyNets "Schematic Supply Nets_1" [InNet('ADC_AVDD')] p24: voltage=0.000
SupplyNets "Schematic Supply Nets" [InNet('VBUS_USB')] p25: voltage=0.000
UnRoutedNet [All] p1: checkbadconnections=TRUE
Width [All] p1: maxlimit=100 minlimit=4 preferedwidth=5 toplayer_maxwidth=40 toplayer_prefwidth=6 midlayer3_maxwidth=40 midlayer3_prefwidth=5.5 midlayer4_maxwidth=40 midlayer4_prefwidth=5.5 bottomlayer_maxwidth=40 bottomlayer_prefwidth=6 impedanceprofiledriven=TRUE impedanceprofileid={F524FB06-5728-4647-A49A-4CD393059D1D} impedanceprofilevalue=50.000000 minimp=50.000000 maximp=50.000000 favimp=50.000000
20 further rules are at their usual default settings.

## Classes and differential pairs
component class 07-STM32WL3-TX: C144 C145 C146 C147 C148 C149 C150 C151 C152 C153 C154 C155 C156 C157 C158 C159 D8 J8 L29 L30 L31 R74 R93 R100 R101 R102 R103 R104 R105 R106 R107 R108 R109 R110 R111 R112 R113 SW3 SW4 U7 U8 Y6 Y7
component class 06-STM32WL3-RX: C128 C129 C130 C131 C132 C133 C134 C135 C136 C137 C138 C139 C140 C141 C142 C143 D2 J7 L26 L27 L28 R72 R73 R75 R76 R78 R81 R82 R83 R84 R85 R86 R87 R88 R89 R90 R91 R92 SW1 SW2 U5 U6 Y3 Y5
component class 11-Ice40_FPGA: C7 C74 C104 C106 C107 D4 R15 R16 R17
component class 06-Si5341_PLL: L16 Y1
component class 08-Power: C1 C35 C36 C37 C38 C40 C41 C42 C44 C45 C48 D3 D4 L9 L10 Q1 Q2 R15 R16 R17 R53 R54 R56 R58 R77 R79 R97 R98 U14
component class 07-USB-Prog: C105 J2 U13
component class 03-8A34004_DPLL-2: C62 C63 C64 C65 C66 C67 C68 C69 C70 C71 C72 C73 C74 C75 C76 C77 C78 C79 C80 C81 C82 C83 C84 C85 C86 C87 C88 C89 C90 C91 C92 C93 C94 C95 C96 C97 C98 C99 C100 C101 C102 C103 C104 C106 C107 C108 C109 C110 C111 C112 C113 C114 C115 L3 L4 L5 L6 L7 L8 L11 L12 L13 L14 L15 L16 R51 R52
component class 02-8A34004_DPLL-1: C55 C58 C59 C60 C61 D1 J1 J3 J5 J6 R18 R19 R20 R21 R22 R23 R24 R25 R30 R31 R32 R33 R34 R35 R36 R37 R38 R39 R40 R41 R42 R44 R45 R46 R47 R48 R49 R50 R71 U10 U11
component class 04-TCXO_Crystal: C21 C22 C23 C24 C25 C26 C27 C54 C56 C57 FB2 L2 R3 R7 R8 R26 R27 R28 R29 R95 R96 Y1 Y4
component class 05-SX1276: C31 C32 C33 C34 C39 C43 C46 C47 C49 C58 C59 C60 C101 C102 C103 C108 C109 C110 C111 C112 C113 C114 C115 L7 L8 L11 L12 L13 L14 L15 R23 R32 R33 R46 R47 R48 R49 R50 R51 R52
component class 04-SX1257: C9 C11 C12 C13 C14 C15 C16 C17 C18 C19 C20 C21 C22 C23 C24 C25 C26 C27 C28 C29 L1 L2 L3 R7 R14 U4 U5
component class 01-Antennas: C2 C3 C4 C5 C6 C7 C8 C9 C10 C11 C12 C13 C14 C15 C16 C17 C18 C19 C20 C28 C29 C30 D5 J4 L1 L17 L18 L19 L20 L21 L22 L23 L24 L25 R1 R2 R4 R5 R6 R9 U1
component class 05-USB-Prog: C31 C32 C33 C34 C39 C43 C46 C47 C49 C50 C51 C52 C53 C105 C116 C117 C118 C119 C120 C121 C122 C123 C124 C125 C126 C127 FB1 FB3 FB4 J2 R10 R11 R12 R13 R14 R55 R57 R59 R60 R61 R62 R63 R64 R65 R66 R67 R68 R69 R70 U2 U3 U4 U13 Y2
component class 01-Antennas: D5 J4
net class RF: NetC4_1 NetC4_2 NetC5_1 NetC8_1 NetC15_1 NetC15_2 NetC16_1 NetC19_1 NetL1_1 NetL21_1 RX_RF RX_RF_RX RX_RF_TX RX_RF_TX_HP TX_RF TX_RF_RX TX_RF_TX TX_RF_TX_HP WIWI_SMA
differential pair U4: +U4_P -U4_N
differential pair U3: +U3_P -U3_N
differential pair USB0_D: +USB0_D_P -USB0_D_N
differential pair TX_FTDI_USB: +TX_FTDI_USB_P -TX_FTDI_USB_N
differential pair RX_FTDI_USB: +RX_FTDI_USB_P -RX_FTDI_USB_N

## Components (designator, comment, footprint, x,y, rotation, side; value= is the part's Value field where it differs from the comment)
C1 "10uF_10V_0402" FP-CL05A106MP5NUNC-MFG 205.71,819.4 r90 bottom value=10uF
C2 "0.1uF_25V_0402" FP-0402-L_1_0_1-W_0_5_0_1-IPC_C 237.64,1662.33 r180 bottom
C3 "100pF_50V_0402" CAPC1005X55X25ML05T10 236.22,1685.04 r90 top
C4 "1.2pF_50V_0402" FP-GJM155-0_05-IPC_A 161.42,1909.45 r90 top
C5 "5pF_50V_0402" FP-GJM155-0_05-IPC_B 271.65,1779.53 r270 top
C6 "5pF_50V_0402" FP-GJM155-0_05-IPC_B 165.35,1842.52 r180 top
C7 "2.2pF_50V_0402" FP-GJM155-0_05-IPC_C 177.32,1976.38 r180 top
C8 "100pF_50V_0402" CAPC1005X55X25ML05T10 211.57,2022.09 r180 top
C9 "0.5pF_50V_0402" FP-GJM155-0_05-MFG 334.65,1980.32 r0 top
C10 "0.5pF_50V_0402" FP-GJM155-0_05-MFG 224.41,2066.93 r180 top
C11 "DNI_0.1uF_16V_0402" FP-C0402-BB-MFG 220.47,2106.3 r180 top value="0.10 μF"
C12 "DNI_0.1uF_16V_0402" FP-C0402-BB-MFG 314.96,2165.35 r90 top value="0.10 μF"
C13 "0.1uF_25V_0402" FP-0402-L_1_0_1-W_0_5_0_1-IPC_C 700.79,1830.71 r90 bottom
C14 "100pF_50V_0402" CAPC1005X55X25ML05T10 637.8,1834.65 r270 bottom
C15 "1.2pF_50V_0402" FP-GJM155-0_05-IPC_A 695.54,2037.39 r90 top
C16 "5pF_50V_0402" FP-GJM155-0_05-IPC_B 564.96,1933.07 r180 top
C17 "5pF_50V_0402" FP-GJM155-0_05-IPC_B 639.74,2035.61 r90 top
C18 "2.2pF_50V_0402" FP-GJM155-0_05-IPC_C 717.81,2102.36 r180 top
C19 "100pF_50V_0402" CAPC1005X55X25ML05T10 738.03,2164.96 r270 top
C20 "0.5pF_50V_0402" FP-GJM155-0_05-MFG 810.41,2250.75 r90 top
C21 "0.1uF_25V_0402" FP-0402-L_1_0_1-W_0_5_0_1-IPC_C 893.7,421.26 r270 top
C22 "10uF_10V_0402" FP-CL05A106MP5NUNC-MFG 1087.17,246.06 r180 top value=10uF
C23 "0.1uF_25V_0402" FP-0402-L_1_0_1-W_0_5_0_1-IPC_C 1158.03,250 r0 top
C24 "10uF_10V_0402" FP-CL05A106MP5NUNC-MFG 977.72,273.76 r270 top value=10uF
C25 "0.1uF_25V_0402" FP-0402-L_1_0_1-W_0_5_0_1-IPC_C 1003.94,358.27 r180 top
C26 "0.1uF_25V_0402" FP-0402-L_1_0_1-W_0_5_0_1-IPC_C 1004.49,403.54 r180 top
C27 "0.1uF_25V_0402" FP-0402-L_1_0_1-W_0_5_0_1-IPC_C 1020.57,273.16 r270 top
C28 "0.5pF_50V_0402" FP-GJM155-0_05-MFG 671.32,2240.78 r90 top
C29 "DNI_0.1uF_16V_0402" FP-C0402-BB-MFG 629.94,2242.51 r90 top value="0.10 μF"
C30 "DNI_0.1uF_16V_0402" FP-C0402-BB-MFG 590.55,2129.92 r270 top value="0.10 μF"
C31 "0.1uF_25V_0402" FP-0402-L_1_0_1-W_0_5_0_1-IPC_C 461.78,672.41 r270 bottom
C32 "0.1uF_25V_0402" FP-0402-L_1_0_1-W_0_5_0_1-IPC_C 586.61,358.27 r270 bottom
C33 "0.1uF_25V_0402" FP-0402-L_1_0_1-W_0_5_0_1-IPC_C 626.07,539.33 r180 bottom
C34 "0.1uF_25V_0402" FP-0402-L_1_0_1-W_0_5_0_1-IPC_C 616.45,622.05 r180 bottom
C35 "0.1uF_16V_0402" FP-C0402-BB-MFG 218.5,897.64 r0 top value="0.10 μF"
C36 "4.7uF_10V_0402" FP-C1005-050-0_15-MFG 210.36,771.14 r0 top
C37 "4.7uF_10V_0402" FP-C1005-050-0_15-MFG 218.5,897.64 r0 bottom
C38 "22uF_10V_0603" CAPC1608X100X20ML10 251.97,834.65 r180 top
C39 "10pF_50V_0402" FP-C1005-050-0_05-IPC_C 685.04,606.3 r90 top
C40 "10uF_10V_0402" FP-CL05A106MP5NUNC-MFG 286.42,916.71 r270 bottom value=10uF
C41 "10uF_10V_0402" FP-CL05A106MP5NUNC-MFG 338.58,918.8 r270 bottom value=10uF
C42 "10uF_10V_0402" FP-CL05A106MP5NUNC-MFG 295.28,712.6 r90 bottom value=10uF
C43 "10pF_50V_0402" FP-C1005-050-0_05-IPC_C 830.71,476.38 r0 top
C44 "10uF_10V_0402" FP-CL05A106MP5NUNC-MFG 350.39,710.63 r90 bottom value=10uF
C45 "22uF_10V_0603" CAPC1608X100X20ML10 303.15,946.85 r90 top
C46 "10nF_50V_0402" FP-CC0402-MFG 246.06,523.62 r90 bottom value="10 nF"
C47 "0.1uF_25V_0402" FP-0402-L_1_0_1-W_0_5_0_1-IPC_C 425.6,570.87 r0 bottom
C48 "22uF_10V_0603" CAPC1608X100X20ML10 303.15,716.54 r270 top
C49 "4.7uF_16V_0402" FP-CL829-IPC_C 425.2,535.43 r0 bottom
C50 "10nF_50V_0402" FP-CC0402-MFG 181.1,1133.86 r0 bottom value="10 nF"
C51 "0.1uF_25V_0402" FP-0402-L_1_0_1-W_0_5_0_1-IPC_C 1011.81,2392.83 r180 bottom
C52 "4.7uF_16V_0402" FP-CL829-IPC_C 1037.64,2354.33 r180 bottom
C53 "47pF_50V_0402" CAPC1005X55X25LL05T10 688.98,476.38 r180 bottom
C54 "0.1uF_50V_0402" FP-C1005-050-0_05-IPC_C 1059.05,510.5 r90 bottom
C55 "0.1uF_25V_0402" FP-0402-L_1_0_1-W_0_5_0_1-IPC_C 51.18,1118.11 r270 bottom
C56 "10uF_25V_0603" FP-CL10-IPC_C 1027.68,649.61 r180 bottom
C57 "0.1uF_50V_0402" FP-C1005-050-0_05-IPC_C 1031.5,606.3 r0 bottom
C58 "10uF_10V_0402" FP-CL05A106MP5NUNC-MFG 677.17,1098.43 r270 bottom value=10uF
C59 "DNI_0.1uF_25V_0402" FP-0402-L_1_0_1-W_0_5_0_1-IPC_C 744.09,491.68 r270 bottom
C60 "DNI_0.1uF_25V_0402" FP-0402-L_1_0_1-W_0_5_0_1-IPC_C 657.48,578.74 r180 bottom
C61 "2.2nF_25V_0402" CAPC1005X56X25LL10T15 818.9,555.12 r180 bottom
C62 "10uF_10V_0402" FP-CL05A106MP5NUNC-MFG 881.07,1248.42 r0 bottom value=10uF
C63 "0.1uF_25V_0402" FP-0402-L_1_0_1-W_0_5_0_1-IPC_C 771.1,1104.89 r270 bottom
C64 "10uF_10V_0402" FP-CL05A106MP5NUNC-MFG 365.1,1064.24 r90 bottom value=10uF
C65 "0.1uF_25V_0402" FP-0402-L_1_0_1-W_0_5_0_1-IPC_C 543.31,996.06 r0 bottom
C66 "0.1uF_25V_0402" FP-0402-L_1_0_1-W_0_5_0_1-IPC_C 322.92,1064.53 r90 bottom
C67 "0.1uF_25V_0402" FP-0402-L_1_0_1-W_0_5_0_1-IPC_C 322.83,996.62 r270 bottom
C68 "10uF_10V_0402" FP-CL05A106MP5NUNC-MFG 641.73,748.03 r0 bottom value=10uF
C69 "0.1uF_25V_0402" FP-0402-L_1_0_1-W_0_5_0_1-IPC_C 629.02,843.97 r0 bottom
C70 "0.1uF_25V_0402" FP-0402-L_1_0_1-W_0_5_0_1-IPC_C 608.76,657.48 r180 bottom
C71 "10uF_10V_0402" FP-CL05A106MP5NUNC-MFG 358.27,1145.67 r90 bottom value=10uF
C72 "0.1uF_25V_0402" FP-0402-L_1_0_1-W_0_5_0_1-IPC_C 653.54,1334.65 r0 bottom
C73 "10uF_10V_0402" FP-CL05A106MP5NUNC-MFG 1030.34,1074.8 r0 bottom value=10uF
C74 "0.1uF_25V_0402" FP-0402-L_1_0_1-W_0_5_0_1-IPC_C 389.76,1358.27 r180 bottom
C75 "0.1uF_25V_0402" FP-0402-L_1_0_1-W_0_5_0_1-IPC_C 883.41,1396.72 r0 bottom
C76 "0.1uF_25V_0402" FP-0402-L_1_0_1-W_0_5_0_1-IPC_C 535.43,681.1 r270 bottom
C77 "10uF_10V_0402" FP-CL05A106MP5NUNC-MFG 984.25,1019.68 r0 bottom value=10uF
C78 "0.1uF_25V_0402" FP-0402-L_1_0_1-W_0_5_0_1-IPC_C 801.72,1001.39 r180 bottom
C79 "0.1uF_25V_0402" FP-0402-L_1_0_1-W_0_5_0_1-IPC_C 1027.38,1120.31 r0 bottom
C80 "10uF_10V_0402" FP-CL05A106MP5NUNC-MFG 574.8,842.2 r90 bottom value=10uF
C81 "0.1uF_25V_0402" FP-0402-L_1_0_1-W_0_5_0_1-IPC_C 531.5,846.07 r90 bottom
C82 "0.1uF_25V_0402" FP-0402-L_1_0_1-W_0_5_0_1-IPC_C 531.5,775.59 r270 bottom
C83 "0.1uF_25V_0402" FP-0402-L_1_0_1-W_0_5_0_1-IPC_C 488.19,744.09 r270 bottom
C84 "10uF_10V_0402" FP-CL05A106MP5NUNC-MFG 574.87,1244.94 r180 bottom value=10uF
C85 "0.1uF_25V_0402" FP-0402-L_1_0_1-W_0_5_0_1-IPC_C 633.86,1110.15 r270 bottom
C86 "0.1uF_25V_0402" FP-0402-L_1_0_1-W_0_5_0_1-IPC_C 651.55,1246 r0 bottom
C87 "10uF_10V_0402" FP-CL05A106MP5NUNC-MFG 799.72,947.91 r180 bottom value=10uF
C88 "0.1uF_25V_0402" FP-0402-L_1_0_1-W_0_5_0_1-IPC_C 1010.79,967.29 r0 bottom
C89 "0.1uF_25V_0402" FP-0402-L_1_0_1-W_0_5_0_1-IPC_C 1011.66,921.35 r0 bottom
C90 "10uF_10V_0402" FP-CL05A106MP5NUNC-MFG 959.51,1306.2 r0 bottom value=10uF
C91 "0.1uF_25V_0402" FP-0402-L_1_0_1-W_0_5_0_1-IPC_C 999.37,1256.41 r0 bottom
C92 "10uF_10V_0402" FP-CL05A106MP5NUNC-MFG 803.15,1039.37 r180 bottom value=10uF
C93 "0.1uF_25V_0402" FP-0402-L_1_0_1-W_0_5_0_1-IPC_C 999.8,1202.03 r0 bottom
C94 "10uF_10V_0402" FP-CL05A106MP5NUNC-MFG 545.41,1104.59 r270 bottom value=10uF
C95 "0.1uF_25V_0402" FP-0402-L_1_0_1-W_0_5_0_1-IPC_C 452.61,1188.06 r90 bottom
C96 "0.1uF_25V_0402" FP-0402-L_1_0_1-W_0_5_0_1-IPC_C 404.08,1188.42 r90 bottom
C97 "10uF_10V_0402" FP-CL05A106MP5NUNC-MFG 861.84,610.33 r270 bottom value=10uF
C98 "0.1uF_25V_0402" FP-0402-L_1_0_1-W_0_5_0_1-IPC_C 771.65,842.52 r90 bottom
C99 "0.1uF_25V_0402" FP-0402-L_1_0_1-W_0_5_0_1-IPC_C 908.58,612.73 r270 bottom
C100 "10uF_10V_0402" FP-CL05A106MP5NUNC-MFG 722.96,1359.19 r180 bottom value=10uF
C101 "0.1uF_25V_0402" FP-0402-L_1_0_1-W_0_5_0_1-IPC_C 721.62,1316.46 r180 bottom
C102 "10uF_10V_0402" FP-CL05A106MP5NUNC-MFG 724.05,1102.91 r270 bottom value=10uF
C103 "0.1uF_25V_0402" FP-0402-L_1_0_1-W_0_5_0_1-IPC_C 725.8,1257.03 r180 bottom
C104 "10uF_10V_0402" FP-CL05A106MP5NUNC-MFG 759.84,638.78 r270 bottom value=10uF
C105 "10uF_16V_0603" FP-0603-L_1_6_0_2-W_0_8_0-MFG 259.84,535.43 r90 top
C106 "0.1uF_25V_0402" FP-0402-L_1_0_1-W_0_5_0_1-IPC_C 799.21,637.8 r270 bottom
C107 "10uF_10V_0402" FP-CL05A106MP5NUNC-MFG 728.35,842.52 r90 bottom value=10uF
C108 "0.1uF_25V_0402" FP-0402-L_1_0_1-W_0_5_0_1-IPC_C 712.6,641.73 r270 bottom
C109 "10uF_10V_0402" FP-CL05A106MP5NUNC-MFG 591.86,1100.8 r270 bottom value=10uF
C110 "0.1uF_25V_0402" FP-0402-L_1_0_1-W_0_5_0_1-IPC_C 458.98,1346.76 r90 bottom
C111 "0.1uF_25V_0402" FP-0402-L_1_0_1-W_0_5_0_1-IPC_C 389.76,1322.83 r180 bottom
C112 "10uF_10V_0402" FP-CL05A106MP5NUNC-MFG 926.72,727.66 r180 bottom value=10uF
C113 "0.1uF_25V_0402" FP-0402-L_1_0_1-W_0_5_0_1-IPC_C 928.52,770.13 r180 bottom
C114 "10uF_10V_0402" FP-CL05A106MP5NUNC-MFG 897.64,850.39 r270 bottom value=10uF
C115 "0.1uF_25V_0402" FP-0402-L_1_0_1-W_0_5_0_1-IPC_C 812.81,892.05 r180 bottom
C116 "47pF_50V_0402" CAPC1005X55X25LL05T10 692.91,358.27 r180 bottom
C117 "10nF_50V_0402" FP-CC0402-MFG 1047.24,2452.76 r180 bottom value="10 nF"
C118 "0.1uF_25V_0402" FP-0402-L_1_0_1-W_0_5_0_1-IPC_C 1190.94,2370.08 r0 bottom
C119 "0.1uF_25V_0402" FP-0402-L_1_0_1-W_0_5_0_1-IPC_C 1110.24,2334.65 r270 bottom
C120 "10nF_50V_0402" FP-CC0402-MFG 186.19,1173.23 r0 bottom value="10 nF"
C121 "0.1uF_25V_0402" FP-0402-L_1_0_1-W_0_5_0_1-IPC_C 213.09,1476 r180 bottom
C122 "4.7uF_16V_0402" FP-CL829-IPC_C 212.6,1511.81 r180 bottom
C123 "47pF_50V_0402" CAPC1005X55X25LL05T10 551.18,464.57 r180 bottom
C124 "47pF_50V_0402" CAPC1005X55X25LL05T10 476.28,464.46 r0 bottom
C125 "10nF_50V_0402" FP-CC0402-MFG 248.03,1409.45 r270 bottom value="10 nF"
C126 "0.1uF_25V_0402" FP-0402-L_1_0_1-W_0_5_0_1-IPC_C 82.68,1590.55 r180 bottom
C127 "0.1uF_25V_0402" FP-0402-L_1_0_1-W_0_5_0_1-IPC_C 138.78,1579.61 r270 bottom
C128 "6.8pF_50V_0402" FP-GJM155-0_05-IPC_A 1133.86,1976.38 r0 bottom
C129 "6.8pF_50V_0402" FP-GJM155-0_05-IPC_A 1007.87,1901.57 r270 bottom
C130 "1uF_16V_0402" FP-0402-L_1_0_0_05-W_0_5-IPC_A 1177.17,1181.1 r270 bottom
C131 "10uF_10V_0402" FP-CL05A106MP5NUNC-MFG 798.23,1200.79 r0 top value=10uF
C132 "0.1uF_25V_0402" FP-0402-L_1_0_1-W_0_5_0_1-IPC_C 795.28,1244.09 r0 top
C133 "10uF_10V_0402" FP-CL05A106MP5NUNC-MFG 864.73,1287.18 r270 top value=10uF
C134 "0.1uF_25V_0402" FP-0402-L_1_0_1-W_0_5_0_1-IPC_C 820.9,1308.34 r270 top
C135 "0.1uF_16V_0402" FP-C0402-BB-MFG 1185.04,2145.67 r90 bottom value="0.10 μF"
C136 "220nF_16V_0402" FP-GRM155-0_05-IPC_C 1032.54,1706.39 r90 bottom
C137 "0.1uF_16V_0402" FP-C0402-BB-MFG 1143.7,1775.57 r180 bottom value="0.10 μF"
C138 "0.1uF_16V_0402" FP-C0402-BB-MFG 950.77,1962.11 r270 bottom value="0.10 μF"
C139 "0.1uF_16V_0402" FP-C0402-BB-MFG 881.89,1905.51 r0 bottom value="0.10 μF"
C140 "4.7uF_10V_0402" FP-C1005-050-0_15-MFG 885.83,1720.47 r90 bottom
C141 "20pF_50V_0402" FP-CBR04C-MFG 888.58,1631.21 r0 bottom value="20 pF"
C142 "4.7uF_10V_0402" FP-C1005-050-0_15-MFG 986.02,1710.57 r90 bottom
C143 "0.1uF_16V_0402" FP-C0402-BB-MFG 939.61,1714.04 r90 bottom value="0.10 μF"
C144 "6.8pF_50V_0402" FP-GJM155-0_05-IPC_A 669.29,1637.8 r270 bottom
C145 "6.8pF_50V_0402" FP-GJM155-0_05-IPC_A 610.24,1637.8 r270 bottom
C146 "1uF_16V_0402" FP-0402-L_1_0_0_05-W_0_5-IPC_A 1007.87,2590.55 r0 bottom
C147 "10uF_10V_0402" FP-CL05A106MP5NUNC-MFG 400.12,1052.98 r180 top value=10uF
C148 "0.1uF_25V_0402" FP-0402-L_1_0_1-W_0_5_0_1-IPC_C 448.82,1102.36 r270 top
C149 "10uF_10V_0402" FP-CL05A106MP5NUNC-MFG 515.75,1228.35 r0 top value=10uF
C150 "0.1uF_25V_0402" FP-0402-L_1_0_1-W_0_5_0_1-IPC_C 360.66,1136.32 r270 top
C151 "0.1uF_16V_0402" FP-C0402-BB-MFG 327.45,1598.43 r90 bottom value="0.10 μF"
C152 "220nF_16V_0402" FP-GRM155-0_05-IPC_C 614.17,1452.76 r90 bottom
C153 "0.1uF_16V_0402" FP-C0402-BB-MFG 738.08,1521 r180 bottom value="0.10 μF"
C154 "0.1uF_16V_0402" FP-C0402-BB-MFG 559.06,1712.6 r270 bottom value="0.10 μF"
C155 "0.1uF_16V_0402" FP-C0402-BB-MFG 480.31,1645.67 r0 bottom value="0.10 μF"
C156 "4.7uF_10V_0402" FP-C1005-050-0_15-MFG 487.2,1456.34 r90 bottom
C157 "20pF_50V_0402" FP-CBR04C-MFG 519.76,1371.64 r90 bottom value="20 pF"
C158 "4.7uF_10V_0402" FP-C1005-050-0_15-MFG 529.34,1454.42 r90 bottom
C159 "0.1uF_16V_0402" FP-C0402-BB-MFG 570.87,1452.76 r90 bottom value="0.10 μF"
D1 "LTST-C190GKT" FP-LTST-C190GKT-MFG 980.31,153.54 r90 top
D2 "LTST-C190GKT" FP-LTST-C190GKT-MFG 673.23,2377.95 r0 top
D3 "LTST-C190GKT" FP-LTST-C190GKT-MFG 385.83,826.77 r0 top
D4 "LTST-C190GKT" FP-LTST-C190GKT-MFG 318.9,551.18 r270 top
D5 "PESD0402-140" FP-PESD0402-MFG 358.27,2303.15 r0 top value=0.25pF
D8 "LTST-C190GKT" FP-LTST-C190GKT-MFG 446.97,1949.06 r180 top
FB1 "600ohm_1.3A_0603" FP-BLM18-0_15-t0_8-IPC_A 311.02,547.24 r90 bottom
FB2 "742792641" FP-742792641-MFG 1137.8,523.62 r180 bottom
FB3 "600ohm_1.3A_0603" FP-BLM18-0_15-t0_8-IPC_A 251.97,1259.84 r90 bottom
FB4 "600ohm_1.3A_0603" FP-BLM18-0_15-t0_8-IPC_A 165.35,1259.84 r90 bottom
J1 "U.FL-R-SMT-1(10)" FP-U_FL-R-SMT-1_10-MFG 472.44,259.84 r180 top
J2 "105017-0001" USB-MICRO-B_V 137.8,417.32 r270 top
J3 "U.FL-R-SMT-1(10)" FP-U_FL-R-SMT-1_10-MFG 803.15,271.65 r180 top
J4 "SMA-J-P-H-ST-MT1" FP-SMA-J-P-H-ST-MT1-MFG 385.83,2492.13 r0 top
J5 "U.FL-R-SMT-1(10)" FP-U_FL-R-SMT-1_10-MFG 1125.98,984.25 r270 top
J6 "U.FL-R-SMT-1(10)" FP-U_FL-R-SMT-1_10-MFG 118.11,1721.46 r90 top
J7 "HTSW-104-07-G-D" FP-HTSW-104-07-G-D-MFG 1129.92,1425.2 r90 top locked
J8 "HTSW-104-07-G-D" FP-HTSW-104-07-G-D-MFG 759.84,2523.62 r180 top
L1 "LQW15AN12NG80D" FP-LQW15AN_80-MFG 297.24,1716.54 r180 top
L2 "742792780" SMD-0402 1114.73,297.24 r180 top
L3 "742792780" SMD-0402 598.43,700.79 r0 bottom
L4 "742792780" SMD-0402 869.04,1322.97 r270 bottom
L5 "742792780" SMD-0402 968.5,1094.49 r270 bottom
L6 "742792780" SMD-0402 615.89,1290.64 r180 bottom
L7 "742792780" SMD-0402 952.76,945.05 r90 bottom
L8 "742792780" SMD-0402 941.69,1231.79 r270 bottom
L9 "DFE252012PD-R47M=P2" FP-DFE252012C-IPC_A 161.42,677.17 r0 top
L10 "DFE252012PD-R47M=P2" FP-DFE252012C-IPC_A 161.42,1011.81 r0 top locked
L11 "742792780" SMD-0402 433.07,1129.92 r0 bottom
L12 "742792780" SMD-0402 885.83,669.29 r180 bottom
L13 "742792780" SMD-0402 783.72,1310.12 r270 bottom
L14 "742792780" SMD-0402 740.16,692.91 r180 bottom
L15 "742792780" SMD-0402 431.16,1287.4 r0 bottom
L16 "742792780" SMD-0402 944.88,841.04 r90 bottom
L17 "LQW15AN7N5G80D" FP-LQW15AN_80-MFG 314.96,1779.72 r90 top
L18 "LQW15AN13NG80D" FP-LQW15AN_80-MFG 228.35,1822.83 r90 top
L19 "LQW15AN13NG80D" FP-LQW15AN_80-MFG 216.54,1917.32 r90 top
L20 "LQW15AN12NG80D" FP-LQW15AN_80-MFG 279.53,2003.94 r90 top
L21 "LQW15AN12NG80D" FP-LQW15AN_80-MFG 673.23,1870.08 r270 top
L22 "LQW15AN7N5G80D" FP-LQW15AN_80-MFG 629.92,1913.39 r90 top
L23 "LQW15AN13NG80D" FP-LQW15AN_80-MFG 590.53,1996.65 r90 top
L24 "LQW15AN13NG80D" FP-LQW15AN_80-MFG 742.93,2035.84 r90 top
L25 "LQW15AN12NG80D" FP-LQW15AN_80-MFG 753.77,2231.89 r180 top
L26 "742792780" SMD-0402 775.84,1315.31 r90 top
L27 "LQM21FN100M80L" FP-LQM21DH_70-IPC_C 962.83,1579.66 r270 top
L28 "LQG15HSR10J02D" FP-LQG15HH_02-IPC_A 898.16,1598.29 r90 top
L29 "742792780" SMD-0402 433.07,1165.35 r180 top
L30 "LQM21FN100M80L" FP-LQM21DH_70-IPC_C 578.55,1315.12 r270 top
L31 "LQG15HSR10J02D" FP-LQG15HH_02-IPC_A 515.75,1319.01 r90 top
Q1 "2N7002KT1G" FP-318-08-MFG 129.17,1015.75 r0 bottom
Q2 "2N7002KT1G" FP-318-08-MFG 114.17,669.29 r180 bottom
R1 "DNI_0_5%_0402" RESC1005X40X25NL05T10 376.97,1691.93 r180 top
R2 "0_5%_0402" RESC1005X40X25NL05T10 376.97,1731.3 r180 top
R3 "100_1%_0402" RESC1005X40X25ML05T10 940.94,421.26 r270 top
R4 "0_5%_0402" RESC1005X40X25NL05T10 257.81,2146.62 r0 top
R5 "DNI_0_5%_0402" RESC1005X40X25NL05T10 736.22,1909.45 r180 top
R6 "0_5%_0402" RESC1005X40X25NL05T10 736.22,1948.82 r180 top
R7 "49.9_1%_0402" RESC1005X40X25NL10T10 1001.7,482.91 r180 top
R8 "100_1%_0402" RESC1005X40X25ML05T10 940.94,507.87 r270 top
R9 "0_5%_0402" RESC1005X40X25NL05T10 629.92,2169.29 r270 top
R10 "649_1%_0402" RESC1005X40X25LL05T05 625.8,502.53 r0 bottom
R11 "27_1%_0402" RESC1005X40X25NL05T05 940.38,2292.19 r180 bottom
R12 "27_1%_0402" RESC1005X40X25NL05T05 980.31,2228.35 r180 bottom
R13 "27_1%_0402" RESC1005X40X25NL05T05 692.91,397.64 r0 bottom
R14 "27_1%_0402" RESC1005X40X25NL05T05 692.91,437.01 r0 bottom
R15 "20K_1%_0402" RESC1005X40X25ML10T10 130.24,773.57 r90 bottom
R16 "330_1%_0402" RESC1005X40X25NL10T10 336.62,822.18 r0 bottom
R17 "330_1%_0402" RESC1005X40X25NL10T10 185.04,594.49 r0 bottom
R18 "4.7K_1%_0402" RESC1005X40X25NL10T10 81.26,1310.97 r180 bottom
R19 "4.7K_1%_0402" RESC1005X40X25NL10T10 83.59,1260.63 r180 bottom
R20 "4.7K_1%_0402" RESC1005X40X25NL10T10 377.95,1240.16 r0 bottom
R21 "DNI_4.7K_1%_0402" RESC1005X40X25NL10T10 291.34,1157.48 r180 bottom
R22 "4.7K_1%_0402" RESC1005X40X25NL10T10 803.15,748.03 r0 top
R23 "4.7K_1%_0402" RESC1005X40X25NL10T10 1137.99,820.02 r180 bottom
R24 "4.7K_1%_0402" RESC1005X40X25NL10T10 291.34,1118.11 r0 bottom
R25 "4.7K_1%_0402" RESC1005X40X25NL10T10 82.68,1208.66 r180 bottom
R26 "49.9_1%_0402" RESC1005X40X25NL10T10 1037.99,840.16 r180 bottom
R27 "4.7K_1%_0402" RESC1005X40X25NL10T10 1171.46,608.07 r0 bottom
R28 "4.7K_1%_0402" RESC1005X40X25NL10T10 1023.62,775.59 r0 bottom
R29 "4.7K_1%_0402" RESC1005X40X25NL10T10 1030.24,713.19 r0 bottom
R30 "DNI_4.7K_1%_0402" RESC1005X40X25NL10T10 318.9,1314.96 r90 bottom
R31 "4.7K_1%_0402" RESC1005X40X25NL10T10 743.63,1580.69 r270 bottom
R32 "4.7K_1%_0402" RESC1005X40X25NL10T10 681.1,748.03 r0 top
R33 "0_5%_0402" RESC1005X40X25NL05T10 464.57,1850.39 r180 bottom
R34 "0_5%_0402" RESC1005X40X25NL05T10 1133.86,1901.57 r180 bottom
R35 "0_5%_0402" RESC1005X40X25NL05T10 633.86,236.22 r270 top
R36 "0_5%_0402" RESC1005X40X25NL05T10 551.85,1319.28 r270 bottom
R37 "0_5%_0402" RESC1005X40X25NL05T10 657.48,972.44 r180 bottom
R38 "0_5%_0402" RESC1005X40X25NL05T10 55.12,1862.2 r270 top
R39 "0_5%_0402" RESC1005X40X25NL05T10 671.8,1190.47 r180 bottom
R40 "0_5%_0402" RESC1005X40X25NL05T10 1186.02,964.57 r90 bottom
R41 "0_5%_0402" RESC1005X40X25NL05T10 1133.38,1844.48 r0 bottom
R42 "0_5%_0402" RESC1005X40X25NL05T10 787.4,153.54 r0 top
R44 "0_5%_0402" RESC1005X40X25NL05T10 492.13,141.73 r0 top
R45 "4.7K_1%_0402" RESC1005X40X25NL10T10 553.23,913.39 r0 bottom
R46 "4.7K_1%_0402" RESC1005X40X25NL10T10 553.23,957.6 r0 bottom
R47 "0_5%_0402" RESC1005X40X25LL10T10 748.03,578.74 r180 bottom
R48 "DNI_1K_1%_0402" RESC1005X40X25NL05T05 748.03,539.37 r180 bottom
R49 "4.7K_1%_0402" RESC1005X40X25NL10T10 413.31,878.76 r180 bottom
R50 "4.7K_1%_0402" RESC1005X40X25NL10T10 413.39,921.26 r180 bottom
R51 "0_5%_0402" RESC1005X40X25LL10T10 271.65,1016.31 r0 bottom
R52 "0_5%_0402" RESC1005X40X25LL10T10 472.44,795.28 r0 bottom
R53 "10K_1%_0402" RESC1005X40X25NL10T10 220.47,1051.18 r90 bottom
R54 "10K_1%_0402" RESC1005X40X25NL10T10 362.2,480.32 r180 bottom
R55 "10K_1%_0402" RESC1005X40X25LL05T10 1080.71,2396.39 r180 bottom
R56 "10K_1%_0402" RESC1005X40X25NL10T10 68.24,816.93 r270 bottom
R57 "0_5%_0402" RESC1005X40X25NL05T10 933.07,2393.7 r180 bottom
R58 "45.3K_1%_0402" RESC0402(1005)_L 133.86,921.26 r270 bottom value="45300.00 Ohm"
R59 "0_5%_0402" RESC1005X40X25NL05T10 992.13,2492.13 r90 top
R60 "15K_1%_0402" FP-ERJ2R-MFG 1161.42,2405.51 r180 bottom value=15kΩ
R61 "0_5%_0402" RESC1005X40X25NL05T10 1181.1,2236.22 r90 top
R62 "27_1%_0402" RESC1005X40X25NL05T05 173.23,1669.29 r90 bottom
R63 "27_1%_0402" RESC1005X40X25NL05T05 31.5,1582.68 r90 top
R64 "27_1%_0402" RESC1005X40X25NL05T05 496.06,374.02 r270 bottom
R65 "27_1%_0402" RESC1005X40X25NL05T05 535.43,374.02 r270 bottom
R66 "10K_1%_0402" RESC1005X40X25LL05T10 295.28,1464.57 r90 bottom
R67 "0_5%_0402" RESC1005X40X25NL05T10 283.46,1610.24 r90 top
R68 "0_5%_0402" RESC1005X40X25NL05T10 232.28,1574.8 r90 bottom
R69 "4.7K_1%_0402" RESC1005X40X25NL10T10 68.99,1380.51 r0 top
R70 "15K_1%_0402" FP-ERJ2R-MFG 192.91,1433.07 r0 bottom value=15kΩ
R71 "330_1%_0402" RESC1005X40X25NL10T10 980.31,157.48 r270 bottom
R72 "330_1%_0402" RESC1005X40X25NL10T10 670.28,2377.95 r180 bottom
R73 "10K_1%_0402" RESC1005X40X25NL10T10 1073.82,1720.39 r90 bottom
R74 "10K_1%_0402" RESC1005X40X25NL10T10 720.17,1440.93 r180 bottom
R75 "10K_1%_0402" RESC1005X40X25NL10T10 1098.43,1196.85 r0 bottom
R76 "0_5%_0402" RESC1005X40X25NL05T10 590.55,1350.39 r270 bottom
R77 "10K_1%_0402" RESC1005X40X25NL10T10 123.03,866.14 r180 bottom
R78 "10K_1%_0402" RESC1005X40X25NL10T10 62.99,2000 r0 bottom
R79 "0_5%_0402" RESC1005X40X25NL05T10 31.5,677.17 r270 bottom
R81 "71.5_1%_0402" RESC1005X40X25NL05T05 846.46,1551.18 r90 top
R82 "0_5%_0402" RESC1005X40X25NL05T10 874.02,1492.13 r180 top
R83 "0_5%_0402" RESC1005X40X25NL05T10 1003.94,2153.54 r0 top
R84 "165_1%_0402" RESC1005X40X25NL05T05 846.64,1627.27 r270 top
R85 "71.5_1%_0402" RESC1005X40X25NL05T05 874.02,2082.68 r0 bottom
R86 "0_5%_0402" RESC1005X40X25NL05T10 807.09,2066.93 r90 bottom
R87 "0_5%_0402" RESC1005X40X25NL05T10 1003.94,2082.68 r0 bottom
R88 "165_1%_0402" RESC1005X40X25NL05T05 937.01,2098.43 r270 bottom
R89 "4.7K_1%_0402" RESC1005X40X25NL10T10 1201.7,1685.77 r270 bottom
R90 "4.7K_1%_0402" RESC1005X40X25NL10T10 1158.27,1686.03 r270 bottom
R91 "DNI_10K_1%_0402" RESC1005X40X25NL10T10 1011.81,1366.14 r90 bottom
R92 "10K_1%_0402" RESC1005X40X25NL10T10 980.31,1496.06 r180 bottom
R93 "330_1%_0402" RESC1005X40X25NL10T10 460.75,1949.06 r0 bottom
R95 "4.7K_1%_0402" RESC1005X40X25NL10T10 1173.23,677.17 r180 bottom
R96 "4.7K_1%_0402" RESC1005X40X25NL10T10 1177.17,751.97 r90 bottom
R97 "DNI_0_5%_0402" RESC1005X40X25NL05T10 31.5,755.91 r270 bottom
R98 "8.06K_1%_0402" RESC1005X40X25ML05T05 49.69,968.5 r270 bottom
R100 "10K_1%_0402" RESC1005X40X25NL10T10 188.98,2377.3 r90 bottom
R101 "10K_1%_0402" RESC1005X40X25NL10T10 185.57,2224.41 r90 bottom
R102 "71.5_1%_0402" RESC1005X40X25NL05T05 388.56,1485.74 r90 bottom
R103 "0_5%_0402" RESC1005X40X25NL05T10 405.51,1429.13 r180 bottom
R104 "0_5%_0402" RESC1005X40X25NL05T10 342.52,1496.06 r270 bottom
R105 "165_1%_0402" RESC1005X40X25NL05T05 386.47,1559.41 r270 bottom
R106 "71.5_1%_0402" RESC1005X40X25NL05T05 385.83,1775.59 r180 bottom
R107 "0_5%_0402" RESC1005X40X25NL05T10 401.57,1834.65 r270 bottom
R108 "0_5%_0402" RESC1005X40X25NL05T10 366.14,1674.21 r270 bottom
R109 "165_1%_0402" RESC1005X40X25NL05T05 382.9,1731.3 r180 bottom
R110 "4.7K_1%_0402" RESC1005X40X25NL10T10 759.84,2377.95 r270 bottom
R111 "4.7K_1%_0402" RESC1005X40X25NL10T10 819.58,1446.49 r270 top
R112 "10K_1%_0402" RESC1005X40X25NL10T10 850.39,2405.51 r180 bottom
R113 "DNI_10K_1%_0402" RESC1005X40X25NL10T10 325.45,1602.36 r90 top
SW1 "B3U-1000P" FP-B3U-1000P-MFG 1141.73,1145.67 r0 top
SW2 "B3U-1000P" FP-B3U-1000P-MFG 82.68,2070.87 r90 top
SW3 "B3U-1000P" FP-B3U-1000P-MFG 118.11,2362.2 r180 top
SW4 "B3U-1000P" FP-B3U-1000P-MFG 118.64,2236.22 r180 top
U1 "SBTC-2-10L+" AT1029_MNC 452.76,2185.79 r0 top
U2 "CY7C65634-28LTXC" CYP-LTX28_M 523.62,586.61 r90 top
U3 "FT231XQ-R" FP-QFN-20-MFG 1036.42,2307.09 r90 top locked
U4 "FT231XQ-R" FP-QFN-20-MFG 153.54,1503.94 r0 top
U5 "STM32WL33CCV7" UFQFPN-48_STM 1010.83,1844.48 r180 top locked
U6 "SN74LVC1G3157DBVR" FP-DBV0006A-IPC_C 1141.73,2122.05 r0 top
U7 "STM32WL33CCV7" UFQFPN-48_STM 609.25,1584.63 r180 top locked
U8 "SN74LVC1G3157DBVR" FP-DBV0006A-IPC_C 349.07,1467.9 r90 top
U10 "24LC1026-I/SN" MCHP-SOIC-SN8_N 182.09,1236.42 r180 top
U11 "8A34004E-000NBG" NBG48P1_REN 673.23,972.44 r0 top locked
U13 "TPD3E001DRYR" DRY0006A 339.17,383.86 r180 bottom
U14 "TPS62442QWRPSRQ1" FP-RQR0014A-MFG 100.71,841.54 r0 top
Y1 "SIT5001AC-3E-33N0-40.000000X" FP-SiT5001-3-MFG 1122.6,433.86 r90 top
Y2 "ABM8G-12.000MHZ-18-D2Y-T" FP-ABM8G-MFG 783.46,574.8 r270 top
Y3 "NX2012SA-32.768KHZ-EXS00A-MU00389" FP-NX2012SA-MFG 1031.5,1974.85 r180 bottom
Y4 "SiTime_SiT5501AC-WU-33E0-10T" SITIME_SPL-086-CQFN-010-C07050_REV_DRAFT 1104.72,725.98 r180 top
Y5 "ASE-48.000MHZ-LC-T" FP-ASE-MFG 925.2,1397.64 r90 top
Y6 "NX2012SA-32.768KHZ-EXS00A-MU00389" FP-NX2012SA-MFG 631.2,1712.6 r180 bottom
Y7 "ASE-48.000MHZ-LC-T" FP-ASE-MFG 417.32,1287.4 r90 top

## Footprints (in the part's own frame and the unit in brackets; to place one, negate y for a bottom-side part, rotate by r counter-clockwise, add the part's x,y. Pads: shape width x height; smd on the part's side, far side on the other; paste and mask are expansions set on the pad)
AT1029_MNC [mil]
  rect 59x8 smd paste+0 mask+0: 1(65.5,50) 2(65.5,0) 3(65.5,-50) 4(-65.5,-50) 6(-65.5,50)
  silkscreen extent -80,-80 152,80
CAPC1005X55X25LL05T10 [mm] "Chip Capacitor, 2-Leads, Body 1.00x0.50mm, IPC High Density"
  rect 0.56x0.52 smd: 1(-0.39,0) 2(0.39,0)
  body extent -0.53,-0.28 0.53,0.28, height 0.55
CAPC1005X55X25ML05T10 [mm] "Chip Capacitor, 2-Leads, Body 1.00x0.50mm, IPC Low Density"
  rect 0.76x0.72 smd: 1(-0.49,0) 2(0.49,0)
  body extent -0.53,-0.28 0.53,0.27, height 0.55
CAPC1005X56X25LL10T15 [mm] "Chip Capacitor, 2-Leads, Body 1.00x0.50mm, IPC High Density"
  rect 0.58x0.54 smd: 1(-0.39,0) 2(0.39,0)
  body extent -0.55,-0.3 0.55,0.3, height 0.56
CAPC1608X100X20ML10 [mm] "Chip Capacitor, 2-Leads, Body 1.70x0.90mm, IPC Low Density"
  rect 0.65x1.05 smd: 1(-0.85,0) 2(0.85,0)
  silkscreen extent -0.15,-0.43 0.15,0.43, body extent -0.85,-0.45 0.85,0.45, height 1
CYP-LTX28_M [mm] "QFN, 28-Leads, Body 5.1x5.1mm, Pitch 0.6mm, Thermal Pad 3.6X3.6mm, IPC Low Density"
  oval 0.85x0.2 smd: 1(-2.575,1.5) 2(-2.575,1) 3(-2.575,0.5) 4(-2.575,0) 5(-2.575,-0.5) 6(-2.575,-1) 7(-2.575,-1.5) 15(2.575,-1.5) 16(2.575,-1) 17(2.575,-0.5) 18(2.575,0) 19(2.575,0.5) 20(2.575,1) 21(2.575,1.5)
  oval 0.2x0.85 smd: 8(-1.5,-2.575) 9(-1,-2.575) 10(-0.5,-2.575) 11(0,-2.575) 12(0.5,-2.575) 13(1,-2.575) 14(1.5,-2.575) 22(1.5,2.575) 23(1,2.575) 24(0.5,2.575) 25(0,2.575) 26(-0.5,2.575) 27(-1,2.575) 28(-1.5,2.575)
  rect 3.5x3.5 smd: 29(0,0)
  silkscreen extent -3.47,-2.7 2.7,2.7, body extent -2.55,-2.55 2.55,2.55, height 0.8
DRY0006A [mm] "SON, 6-Leads, Body 1.45x1mm, Pitch 0.5mm"
  rrect33% 0.52x0.3 smd: 1(-0.37,0.5)
  rrect33% 0.49x0.3 smd: 2(-0.385,0) 3(-0.385,-0.5) 4(0.385,-0.5) 5(0.385,0) 6(0.385,0.5)
  silkscreen extent -1.08,0.45 -0.98,0.55, body extent -0.5,-0.72 0.5,0.72, height 0.6
FP-318-08-MFG [mm]
  rect 0.9x0.8 smd paste+0 mask+0: 1(-1,0.95) 2(-1,-0.95) 3(1,0)
  silkscreen extent -0.7,-1.52 0.7,1.52, body extent -1.2,-1.45 1.2,1.45, height 1.11
FP-0402-L_1_0_0_05-W_0_5-IPC_A [mil]
  rect 28.16x26.48 smd paste+0 mask+0: 1(-18.84,0) 2(18.84,0)
  silkscreen extent -33,-29 33,29, body extent -20,-10 20,10, height 22
FP-0402-L_1_0_1-W_0_5_0_1-IPC_C [mil]
  rect 22.88x20.16 smd paste+0 mask+0: 1(-14.39,0) 2(14.39,0)
  silkscreen extent -26,-28 26,28, body extent -20,-10 20,10, height 22
FP-0603-L_1_6_0_2-W_0_8_0-MFG [mm]
  rect 0.7x0.7 smd paste+0 mask+0: 1(-0.7,0) 2(0.7,0)
  body extent -1.15,-0.6 1.15,0.6, height 0.25
FP-742792641-MFG [mm]
  rect 0.95x0.7 smd paste+0 mask+0: 1(-0.825,0) 2(0.825,0)
  body extent -0.8,-0.4 0.8,0.4, height 1
FP-ABM8G-MFG [mm]
  rect 1.4x1.2 smd paste+0 mask+0: 1(-1.1,-0.85) 2(1.1,-0.85) 3(1.1,0.85) 4(-1.1,0.85)
  silkscreen extent -2.47,-1.83 1.6,1.83, body extent -1.9,-1.55 1.9,1.55, height 0.25
FP-ASE-MFG [mm]
  rect 1.3x1.1 smd paste+0 mask+0: 1(-1.05,-0.825) 2(1.05,-0.825) 3(1.05,0.825) 4(-1.05,0.825)
  silkscreen extent -2.07,-2.05 2.07,1.35, body extent -1.8,-1.48 1.8,1.48, height 0.25
FP-B3U-1000P-MFG [mm]
  rect 0.8x1.7 smd paste+0 mask+0: 1(-1.7,0) 2(1.7,0)
  silkscreen extent -1.6,-1.35 1.6,1.35, body extent -2,-1.26 2,1.24, height 1.6
FP-BLM18-0_15-t0_8-IPC_A [mil]
  rect 51.42x41.66 smd paste+0 mask+0: 1(-30.55,0) 2(30.55,0)
  silkscreen extent -56,-37 56,37, body extent -31,-16 31,16, height 37
FP-C0402-BB-MFG [mm]
  rect 0.52x0.52 smd paste+0 mask+0: 1(-0.4,0) 2(0.4,0)
  silkscreen extent -0.5,-0.64 0.5,0.64, body extent -0.8,-0.4 0.8,0.4, height 0.25
FP-C1005-050-0_05-IPC_C [mil]
  rect 21.23x18.6 smd paste+0 mask+0: 1(-14.43,0) 2(14.43,0)
  silkscreen extent -25,-27 25,27, body extent -20,-10 20,10, height 22
FP-C1005-050-0_15-MFG [mm]
  rect 0.4x0.5 smd paste+0 mask+0: 1(-0.4,0) 2(0.4,0)
  silkscreen extent -0.5,-0.72 0.5,0.72, body extent -0.5,-0.25 0.5,0.25, height 0.55
FP-CBR04C-MFG [mm]
  rect 0.52x0.52 smd paste+0 mask+0: 1(-0.4,0) 2(0.4,0)
  silkscreen extent -0.53,-0.68 0.53,0.67, body extent -0.5,-0.25 0.5,0.25, height 0.55
FP-CC0402-MFG [mm]
  rect 0.5x0.5 smd paste+0 mask+0: 1(-0.5,0) 2(0.5,0)
  silkscreen extent -0.53,-0.68 0.53,0.67, body extent -0.5,-0.25 0.5,0.25, height 0.55
FP-CL05A106MP5NUNC-MFG [mm]
  rect 0.45x0.675 smd paste+0 mask+0: 1(-0.463,0) 2(0.463,0)
  body extent -0.5,-0.25 0.5,0.25, height 0.7
FP-CL10-IPC_C [mil]
  rect 29.85x31.97 smd paste+0 mask+0: 1(-24.68,0) 2(24.69,0)
  body extent -31,-16 31,16, height 36
FP-CL829-IPC_C [mil]
  rect 20.29x18.6 smd paste+0 mask+0: 1(-14.9,0) 2(14.9,0)
  silkscreen extent -25,-27 25,27, body extent -20,-10 20,10, height 22
FP-DBV0006A-IPC_C [mm]
  rect 1.205x0.53 smd paste+0 mask+0: 1(-1.05,0.95)
  rrect100% 1.205x0.53 smd paste+0 mask+0: 2(-1.05,0) 3(-1.05,-0.95) 4(1.05,-0.95) 5(1.05,0) 6(1.05,0.95)
  silkscreen extent -2.33,-1.45 0.05,1.45, body extent -1.75,-1.55 1.75,1.55, height 0.25
FP-DFE252012C-IPC_A [mil]
  rect 61.22x90.8 smd paste+0 mask+0: 1(-44.32,0) 2(44.32,0)
  silkscreen extent -75,-61 75,61, body extent -95,-65 95,65, height 10
FP-ERJ2R-MFG [mm]
  rect 0.475x0.5 smd paste+0 mask+0: 1(-0.512,0) 2(0.513,0)
  silkscreen extent -0.53,-0.64 0.53,0.65, body extent -0.5,-0.25 0.5,0.25, height 0.4
FP-GJM155-0_05-IPC_A [mil]
  rect 28.16x26.48 smd paste+0 mask+0: 1(-18.84,0) 2(18.84,0)
  silkscreen extent -33,-29 33,29, body extent -41,-21 41,21, height 10
FP-GJM155-0_05-IPC_B [mil]
  rect 24.23x22.54 smd paste+0 mask+0: 1(-16.87,0) 2(16.87,0)
  silkscreen extent -29,-27 29,27, body extent -20,-10 20,10, height 22
FP-GJM155-0_05-IPC_C [mil]
  rect 20.29x18.6 smd paste+0 mask+0: 1(-14.9,0) 2(14.9,0)
  silkscreen extent -25,-27 25,27, body extent -29,-15 29,15, height 10
FP-GJM155-0_05-MFG [mm]
  rect 0.4x0.5 smd paste+0 mask+0: 1(-0.4,0) 2(0.4,0)
  silkscreen extent -0.53,-0.63 0.53,0.63, body extent -0.7,-0.38 0.7,0.38, height 0.25
FP-GRM155-0_05-IPC_C [mil]
  rect 20.29x18.6 smd paste+0 mask+0: 1(-14.9,0) 2(14.9,0)
  silkscreen extent -25,-27 25,27, body extent -20,-10 20,10, height 22
FP-HTSW-104-07-G-D-MFG [mm]
  rect 1.57x1.57 hole 1.02 paste-2539.97 mask+0: 1(-3.81,-1.27)
  round 1.57 hole 1.02 paste-2539.97 mask+0: 2(-3.81,1.27) 3(-1.27,-1.27) 4(-1.27,1.27) 5(1.27,-1.27) 6(1.27,1.27) 7(3.81,-1.27) 8(3.81,1.27)
  silkscreen extent -5.87,-2.58 5.14,2.58, body extent -5.08,-2.51 5.08,2.51, height 8.71
FP-LQG15HH_02-IPC_A [mil]
  rect 28.16x26.48 smd paste+0 mask+0: 1(-18.84,0) 2(18.84,0)
  silkscreen extent -65,-29 33,29, body extent -20,-10 20,10, height 22
FP-LQM21DH_70-IPC_C [mil]
  rect 45.45x53.39 smd paste+0 mask+0: 1(-26.61,0) 2(26.61,0)
  silkscreen extent -49,-44 49,44, body extent -53,-32 53,32, height 10
FP-LQW15AN_80-MFG [mm]
  rect 0.41x0.66 smd paste+0 mask+0: 1(-0.505,0) 2(0.505,0)
  silkscreen extent -0.56,-0.74 0.55,0.75, body extent -0.81,-0.45 0.81,0.45, height 0.25
FP-LTST-C190GKT-MFG [mm]
  rect 0.8x0.8 smd paste+0 mask+0: 1(-0.75,0) 2(0.75,0)
  silkscreen extent -1.92,-0.85 0.85,0.85, body extent -1.25,-0.55 1.25,0.55, height 0.25
FP-NX2012SA-MFG [mm]
  rect 1x1.25 smd paste+0 mask+0: 1(-0.75,0) 2(0.75,0)
  silkscreen extent -0.6,-1.02 0.6,1.02, body extent -1.02,-0.6 1.02,0.6, height 0.6
FP-PESD0402-MFG [mm]
  rect 0.85x0.65 smd paste+0 mask+0: 1(-0.625,0) 2(0.625,0)
  body extent -1.15,-0.43 1.15,0.43, height 0.25
FP-QFN-20-MFG [mm]
  rect 0.8x0.25 smd paste+0 mask+0: 1(-2.025,1)
  rrect100% 0.8x0.25 smd paste+0 mask+0: 2(-2.025,0.5) 3(-2.025,0) 4(-2.025,-0.5) 5(-2.025,-1) 11(2.025,-1) 12(2.025,-0.5) 13(2.025,0) 14(2.025,0.5) 15(2.025,1)
  rrect100% 0.25x0.8 smd paste+0 mask+0: 6(-1,-2.025) 7(-0.5,-2.025) 8(0,-2.025) 9(0.5,-2.025) 10(1,-2.025) 16(1,2.025) 17(0.5,2.025) 18(0,2.025) 19(-0.5,2.025) 20(-1,2.025)
  rect 2.6x2.6 smd paste+0 mask+0: 21(0,0)
  silkscreen extent -3.15,-2 2,2, body extent -2.52,-2.52 2.52,2.52, height 0.25
FP-RQR0014A-MFG [mm]
  rrect40% 0.625x0.25 smd paste+0 mask+0: 1(-1.038,0.5) 2(-1.038,0) 3(-1.038,-0.5) 8(1.038,-0.5) 10(1.038,0.5)
  rrect40% 0.25x0.675 smd paste+0 mask+0: 4(-0.75,-1.212) 5(-0.25,-1.212) 7(0.75,-1.212) 11(0.75,1.212) 13(-0.25,1.212) 14(-0.75,1.212)
  rrect40% 0.25x0.975 smd paste+0 mask+0: 6(0.25,-1.062) 12(0.25,1.062)
  rrect40% 1.225x0.25 smd paste+0 mask+0: 9(0.737,0)
  silkscreen extent -2.2,-1.55 1.35,2.39, body extent -1.45,-1.65 1.45,1.65, height 0.25
FP-SiT5001-3-MFG [mm]
  rect 1.5x1.6 smd paste+0 mask+0: 1(-1.27,-1.1) 2(1.27,-1.1) 3(1.27,1.1) 4(-1.27,1.1)
  silkscreen extent -2.52,-2.58 2.52,1.63, body extent -2.63,-2 2.63,2, height 0.25
FP-SMA-J-P-H-ST-MT1-MFG [mm]
  round 1.73 smd paste+0 mask+0: 1(0,0)
  round 2.3 hole 1.5 paste-2539.97 mask+0: 2(-2.665,2.665) 3(2.665,2.665) 4(-2.665,-2.665) 5(2.665,-2.665)
  silkscreen extent -3.96,-3.24 3.24,3.24, body extent -3.92,-3.92 3.92,3.92, height 0.25
FP-U_FL-R-SMT-1_10-MFG [mm]
  rect 1x1.05 smd paste-1000 mask+0: 1(0,1.525)
  rect 1.05x2.2 smd paste-1000 mask+0: 2(-1.475,0) 3(1.475,0)
  silkscreen extent -0.58,-1.38 0.58,-1.38, body extent -2.1,-1.48 2.1,2.15, height 0.25
MCHP-SOIC-SN8_N [mm] "SOIC, 8-Leads, Body 4.9x3.9mm, Pitch 1.27mm, IPC Medium Density"
  oval 2.05x0.6 smd: 1(-2.425,1.905) 2(-2.425,0.635) 3(-2.425,-0.635) 4(-2.425,-1.905) 5(2.425,-1.905) 6(2.425,-0.635) 7(2.425,0.635) 8(2.425,1.905)
  silkscreen extent -2.55,-2.45 1,2.88, body extent -1.95,-2.45 1.95,2.45, height 1.75
NBG48P1_REN [mil]
  rect 32x10 smd paste+0 mask+0: 1(-136,108.27) 2(-136,88.58) 3(-136,68.9) 4(-136,49.21) 5(-136,29.53) 6(-136,9.84) 7(-136,-9.84) 8(-136,-29.53) 9(-136,-49.21) 10(-136,-68.9) 11(-136,-88.58) 12(-136,-108.27) 25(136,-108.27) 26(136,-88.58) 27(136,-68.9) 28(136,-49.21) 29(136,-29.53) 30(136,-9.84) 31(136,9.84) 32(136,29.53) 33(136,49.21) 34(136,68.9) 35(136,88.58) 36(136,108.27)
  rect 10x32 smd paste+0 mask+0: 13(-108.27,-136) 14(-88.58,-136) 15(-68.9,-136) 16(-49.21,-136) 17(-29.53,-136) 18(-9.84,-136) 19(9.84,-136) 20(29.53,-136) 21(49.21,-136) 22(68.9,-136) 23(88.58,-136) 24(108.27,-136) 37(108.27,136) 38(88.58,136) 39(68.9,136) 40(49.21,136) 41(29.53,136) 42(9.84,136) 43(-9.84,136) 44(-29.53,136) 45(-49.21,136) 46(-68.9,136) 47(-88.58,136) 48(-108.27,136)
  rect 226x226 smd paste-113 mask+0: 49(0,0)
  silkscreen extent -172,-172 172,172, body extent -140,-140 140,140, height 32
RESC0402(1005)_L [mm] "Chip Resistor, Body 1.0x0.5mm, IPC High Density"
  rect 0.45x0.55 smd: 1(-0.45,0) 2(0.45,0)
  body extent -0.52,-0.27 0.53,0.28, height 0.4
RESC1005X40X25LL05T05 [mm] "Chip Resistor, 2-Leads, Body 1.00x0.50mm, IPC High Density"
  rect 0.45x0.45 smd: 1(-0.4,0) 2(0.4,0)
  body extent -0.53,-0.27 0.53,0.28, height 0.4
RESC1005X40X25LL05T10 [mm] "Chip Resistor, 2-Leads, Body 1.00x0.50mm, IPC High Density"
  rect 0.5x0.45 smd: 1(-0.375,0) 2(0.375,0)
  body extent -0.53,-0.27 0.53,0.28, height 0.4
RESC1005X40X25LL10T10 [mm] "Chip Resistor, 2-Leads, Body 1.00x0.50mm, IPC High Density"
  rect 0.55x0.5 smd: 1(-0.375,0) 2(0.375,0)
  body extent -0.55,-0.3 0.55,0.3, height 0.4
RESC1005X40X25ML05T05 [mm] "Chip Resistor, 2-Leads, Body 1.05x0.55mm, IPC Low Density"
  rect 0.65x0.65 smd: 1(-0.5,0) 2(0.5,0)
  body extent -0.53,-0.28 0.53,0.28, height 0.4
RESC1005X40X25ML05T10 [mm] "Chip Resistor, 2-Leads, Body 1.00x0.50mm, IPC Low Density"
  rect 0.7x0.65 smd: 1(-0.475,0) 2(0.475,0)
  body extent -0.53,-0.27 0.53,0.28, height 0.4
RESC1005X40X25ML10T10 [mm] "Chip Resistor, 2-Leads, Body 1.00x0.50mm, IPC Low Density"
  rect 0.75x0.7 smd: 1(-0.475,0) 2(0.475,0)
  body extent -0.55,-0.3 0.55,0.3, height 0.4
RESC1005X40X25NL05T05 [mm] "Chip Resistor, 2-Leads, Body 1.00x0.50mm, IPC Medium Density"
  rect 0.55x0.55 smd: 1(-0.45,0) 2(0.45,0)
  body extent -0.53,-0.27 0.53,0.28, height 0.4
RESC1005X40X25NL05T10 [mm] "Chip Resistor, 2-Leads, Body 1.00x0.50mm, IPC Medium Density"
  rect 0.6x0.55 smd: 1(-0.425,0) 2(0.425,0)
  body extent -0.53,-0.27 0.53,0.28, height 0.4
RESC1005X40X25NL10T10 [mm] "Chip Resistor, 2-Leads, Body 1.00x0.50mm, IPC Medium Density"
  rect 0.65x0.6 smd: 1(-0.425,0) 2(0.425,0)
  body extent -0.55,-0.3 0.55,0.3, height 0.4
SITIME_SPL-086-CQFN-010-C07050_REV_DRAFT [mm] "Package information (Page 9): https://www.sitime.com/support/resource-library/datasheets/sit5501-datasheet"
  rect 0.85x1.25 smd paste+0 mask+0.05: 1(-1.27,2.875) 5(-1.27,-2.875) 6(1.27,-2.875) 10(1.27,2.875)
  rect 1.25x0.65 smd paste+0 mask+0.05: 2(-1.875,1.27) 3(-1.875,0) 4(-1.875,-1.27) 7(1.875,-1.27) 8(1.875,0) 9(1.875,1.27)
  silkscreen extent -2.6,-3.5 2.6,3.5, body extent -2.5,-3.5 2.5,3.5, height 2.3
SMD-0402 [mm] "Chip Inductor, 2-Leads, Body 1.0x0.5mm"
  rect 0.675x0.6 smd: 1(-0.6,0) 2(0.6,0)
  body extent -0.5,-0.25 0.5,0.25, height 0.49
UFQFPN-48_STM [mm]
  rect 0.55x0.3 smd paste-0.15 mask-0.279: 1(-3.375,2.751) 2(-3.375,2.251) 3(-3.375,1.75) 4(-3.375,1.25) 5(-3.375,0.75) 6(-3.375,0.25) 7(-3.375,-0.25) 8(-3.375,-0.75) 9(-3.375,-1.25) 10(-3.375,-1.75) 11(-3.375,-2.251) 12(-3.375,-2.751) 25(3.375,-2.751) 26(3.375,-2.251) 27(3.375,-1.75) 28(3.375,-1.25) 29(3.375,-0.75) 30(3.375,-0.25) 31(3.375,0.25) 32(3.375,0.75) 33(3.375,1.25) 34(3.375,1.75) 35(3.375,2.251) 36(3.375,2.751)
  rect 0.3x0.55 smd paste-0.15 mask-0.279: 13(-2.75,-3.375) 14(-2.25,-3.375) 15(-1.75,-3.375) 16(-1.25,-3.375) 17(-0.75,-3.375) 18(-0.25,-3.375) 19(0.25,-3.375) 20(0.75,-3.375) 21(1.25,-3.375) 22(1.75,-3.375) 23(2.25,-3.375) 24(2.75,-3.375) 37(2.75,3.375) 38(2.25,3.375) 39(1.75,3.375) 40(1.25,3.375) 41(0.75,3.375) 42(0.25,3.375) 43(-0.25,3.375) 44(-0.75,3.375) 45(-1.25,3.375) 46(-1.75,3.375) 47(-2.25,3.375) 48(-2.75,3.375)
  rect 5.6x5.6 smd paste-2.8 mask-2.794: 49(0,0)
  L01-TOP region: 0,-2.8 0,-2.8 0,-2.8 0,-2.8 0,-2.8 0,-2.8 0,-2.8 0,-2.8
  L01-TOP region: 0,2.8 0,2.8 0,2.8 0,2.8 0,2.8 0,2.8 0,2.8 0,2.8
  silkscreen extent -4.16,-4.16 4.16,4.16
USB-MICRO-B_V [mm] "USB, MICRO B, Body 7.491x4.695 mm, Pitch 0.65 mm"
  rect 0.4x1.35 smd: 1(-1.3,1.35) 2(-0.65,1.35) 3(0,1.35) 4(0.65,1.35) 5(1.3,1.35)
  round 1.45 hole 0.85: 6(-2.5,1.35) 7(2.5,1.35)
  rrect50% 0x0 hole 0.6 slot 1.3 at 90 deg: 8(-3.5,-1.35) 11(3.5,-1.35)
  rect 1.5x1.9 smd: 9(-1,-1.35) 10(1,-1.35)
  L01-TOP circle w0.5: c3.6,-0.9 r0.25
  L01-TOP circle w0.5: c3.6,-1.8 r0.25
  L01-TOP circle w0.5: c-3.6,-0.9 r0.25
  L01-TOP circle w0.5: c-3.6,-1.8 r0.25
  L01-TOP region: -2.3,-2.3 -2.3,-0.4 -3.6,-0.4 -3.6,-2.3
  L01-TOP region: 2.3,-0.4 2.3,-2.3 3.6,-2.3 3.6,-0.4
  L01-TOP region: 3.6,-0.9 3.6,-1.8 4.1,-1.8 4.1,-0.9
  L01-TOP region: -3.6,-1.8 -3.6,-0.9 -4.1,-0.9 -4.1,-1.8
  silkscreen extent -3.75,-3.5 3.75,2.23, body extent -4.1,-3.9 4.1,1.5, height 2.67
